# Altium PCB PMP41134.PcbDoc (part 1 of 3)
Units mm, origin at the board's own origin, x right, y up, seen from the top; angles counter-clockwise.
Board outline 252.04 x 132.61 mm, 6 copper layers (Top Layer, Layer 1, Layer 2, Layer 3, Layer 4, Bottom Layer), stack 2.208 mm thick; 221 components, 92 nets, 680 pads, 1197 vias.
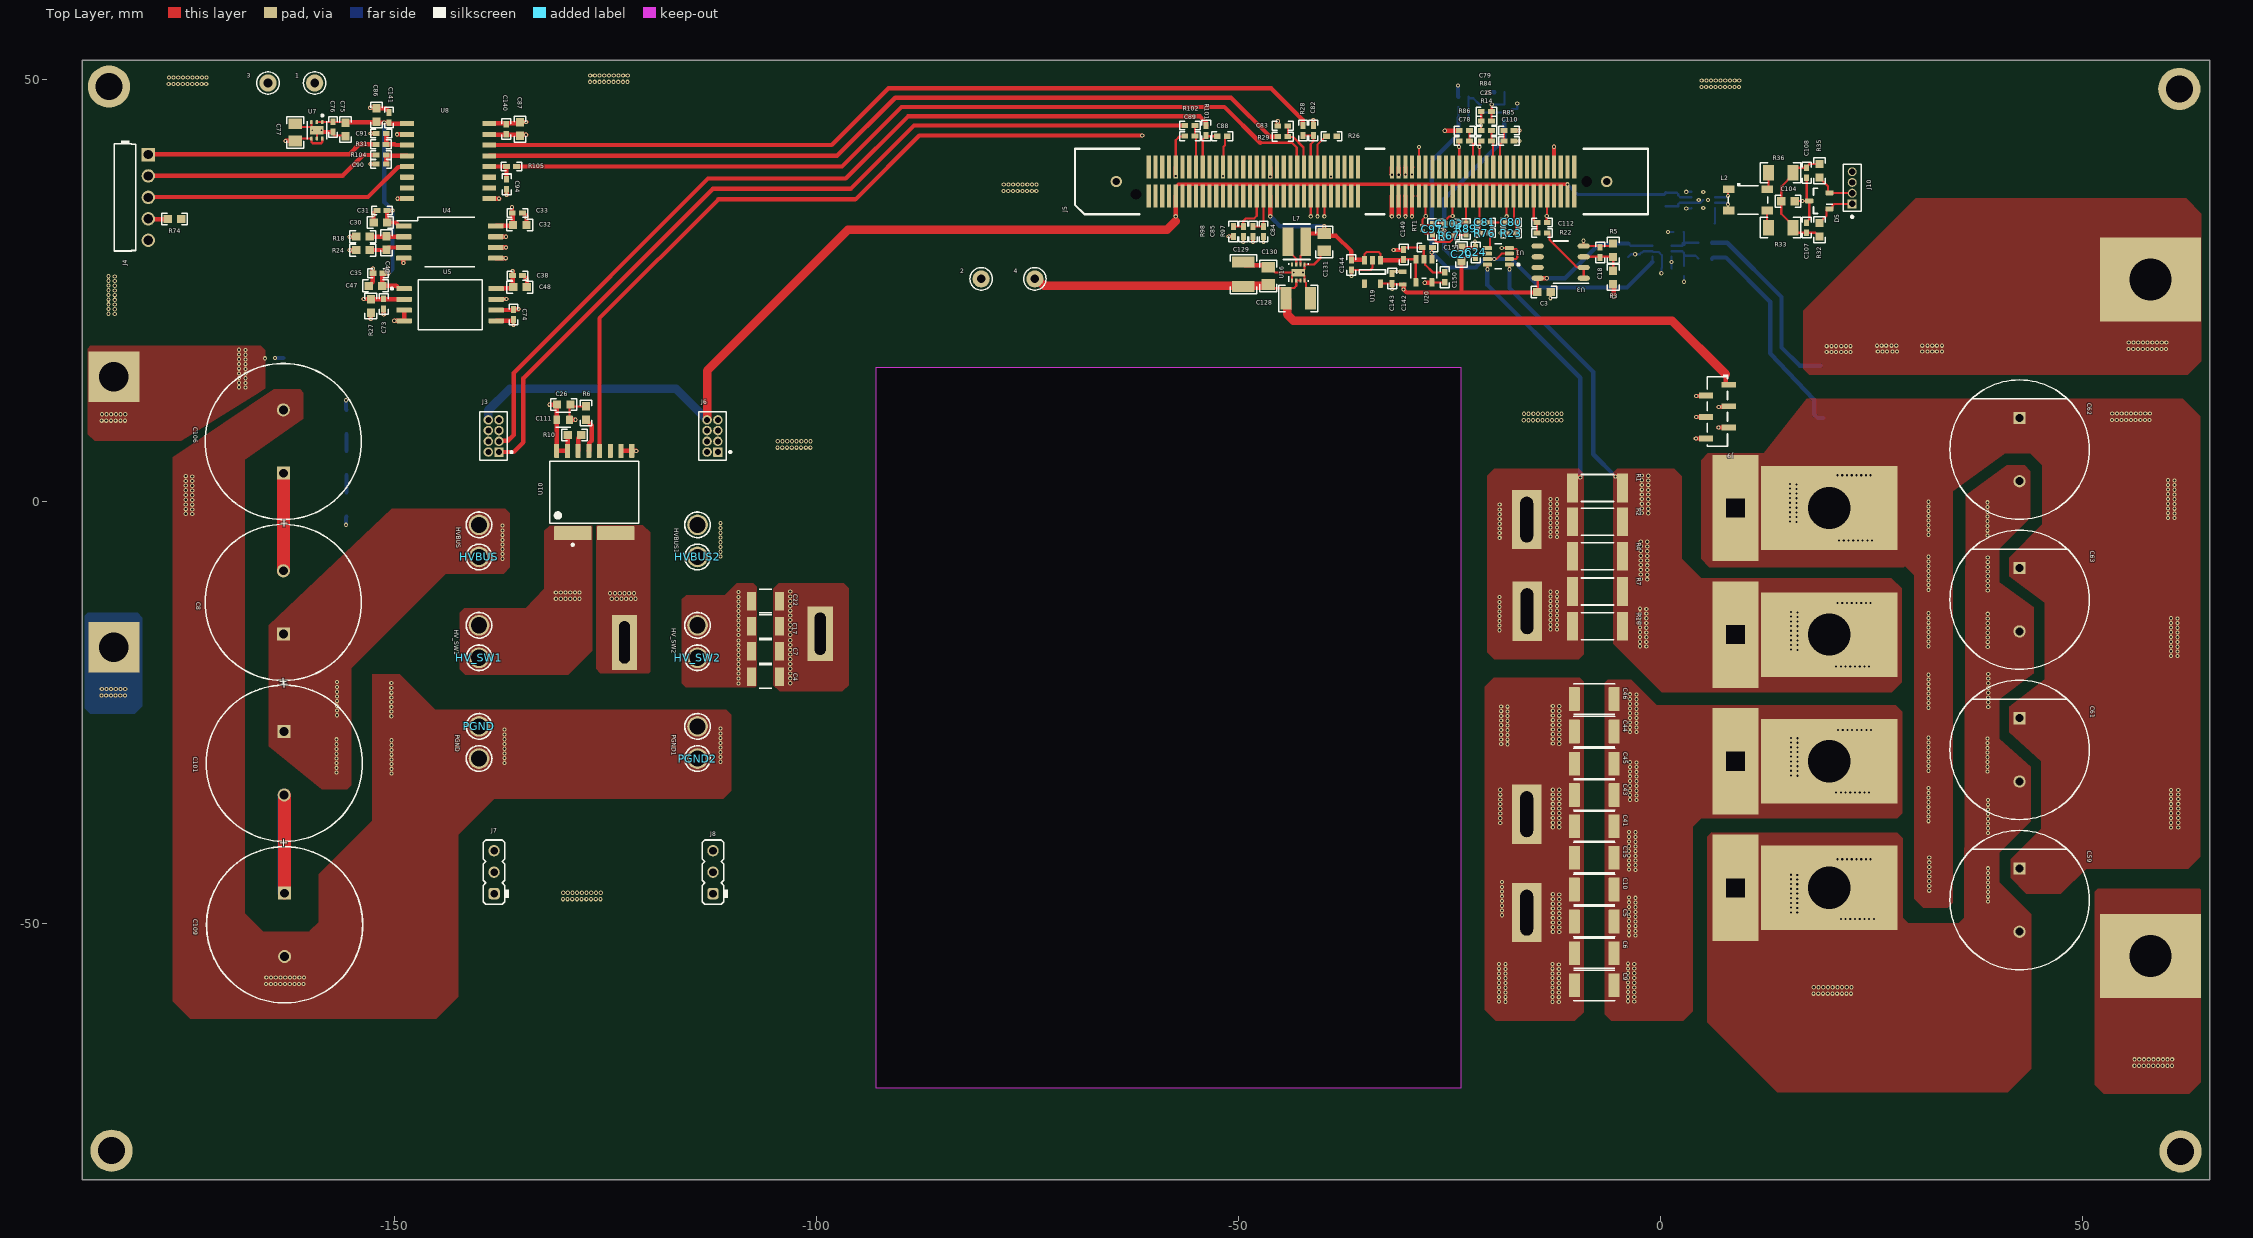
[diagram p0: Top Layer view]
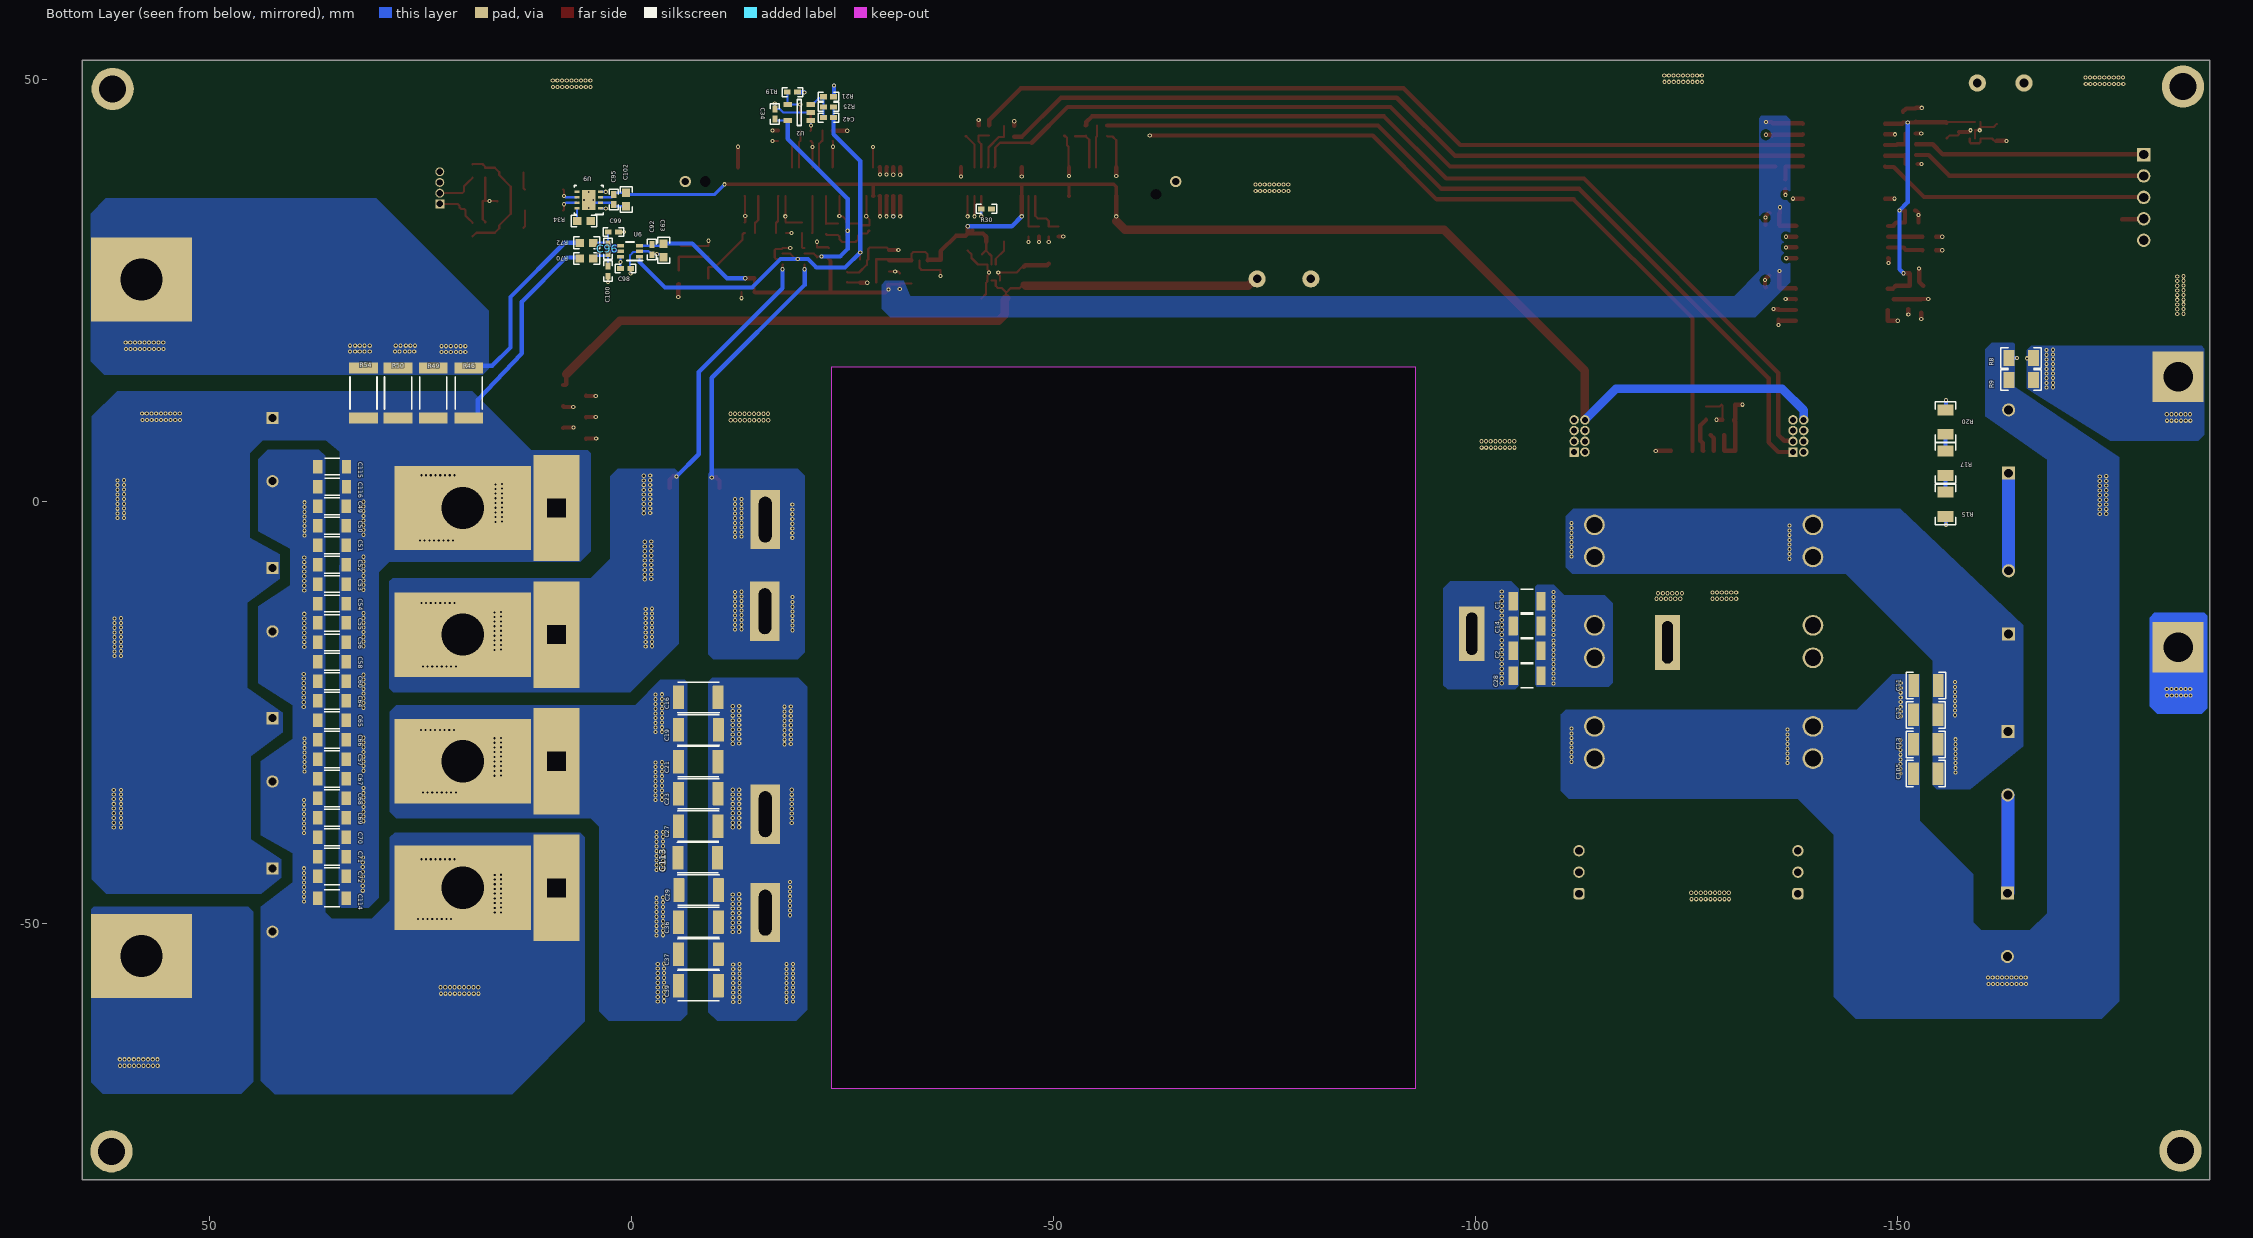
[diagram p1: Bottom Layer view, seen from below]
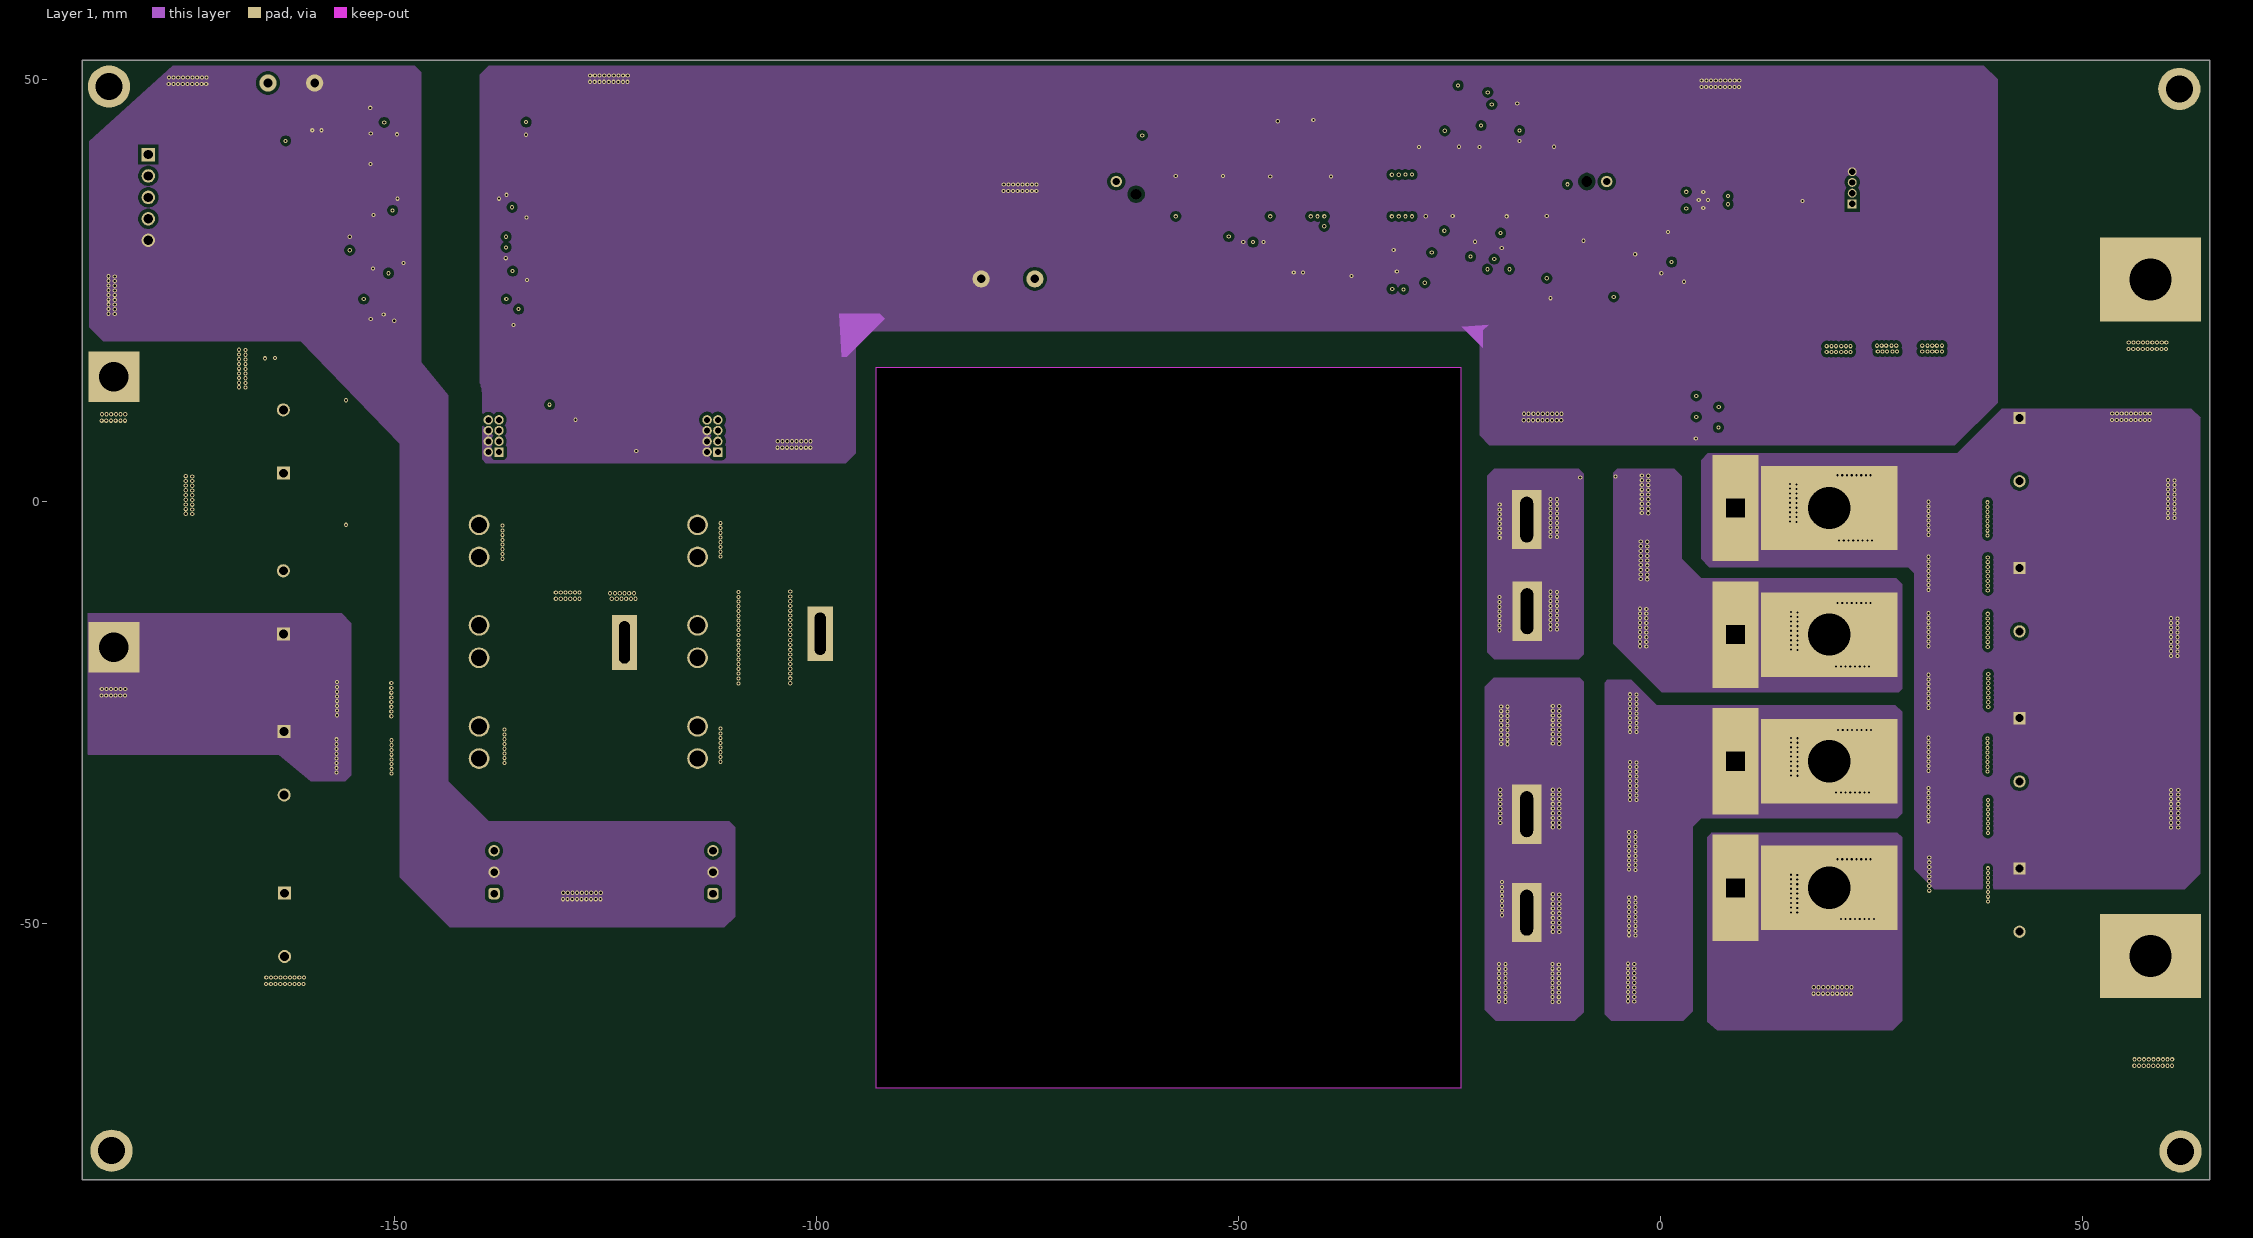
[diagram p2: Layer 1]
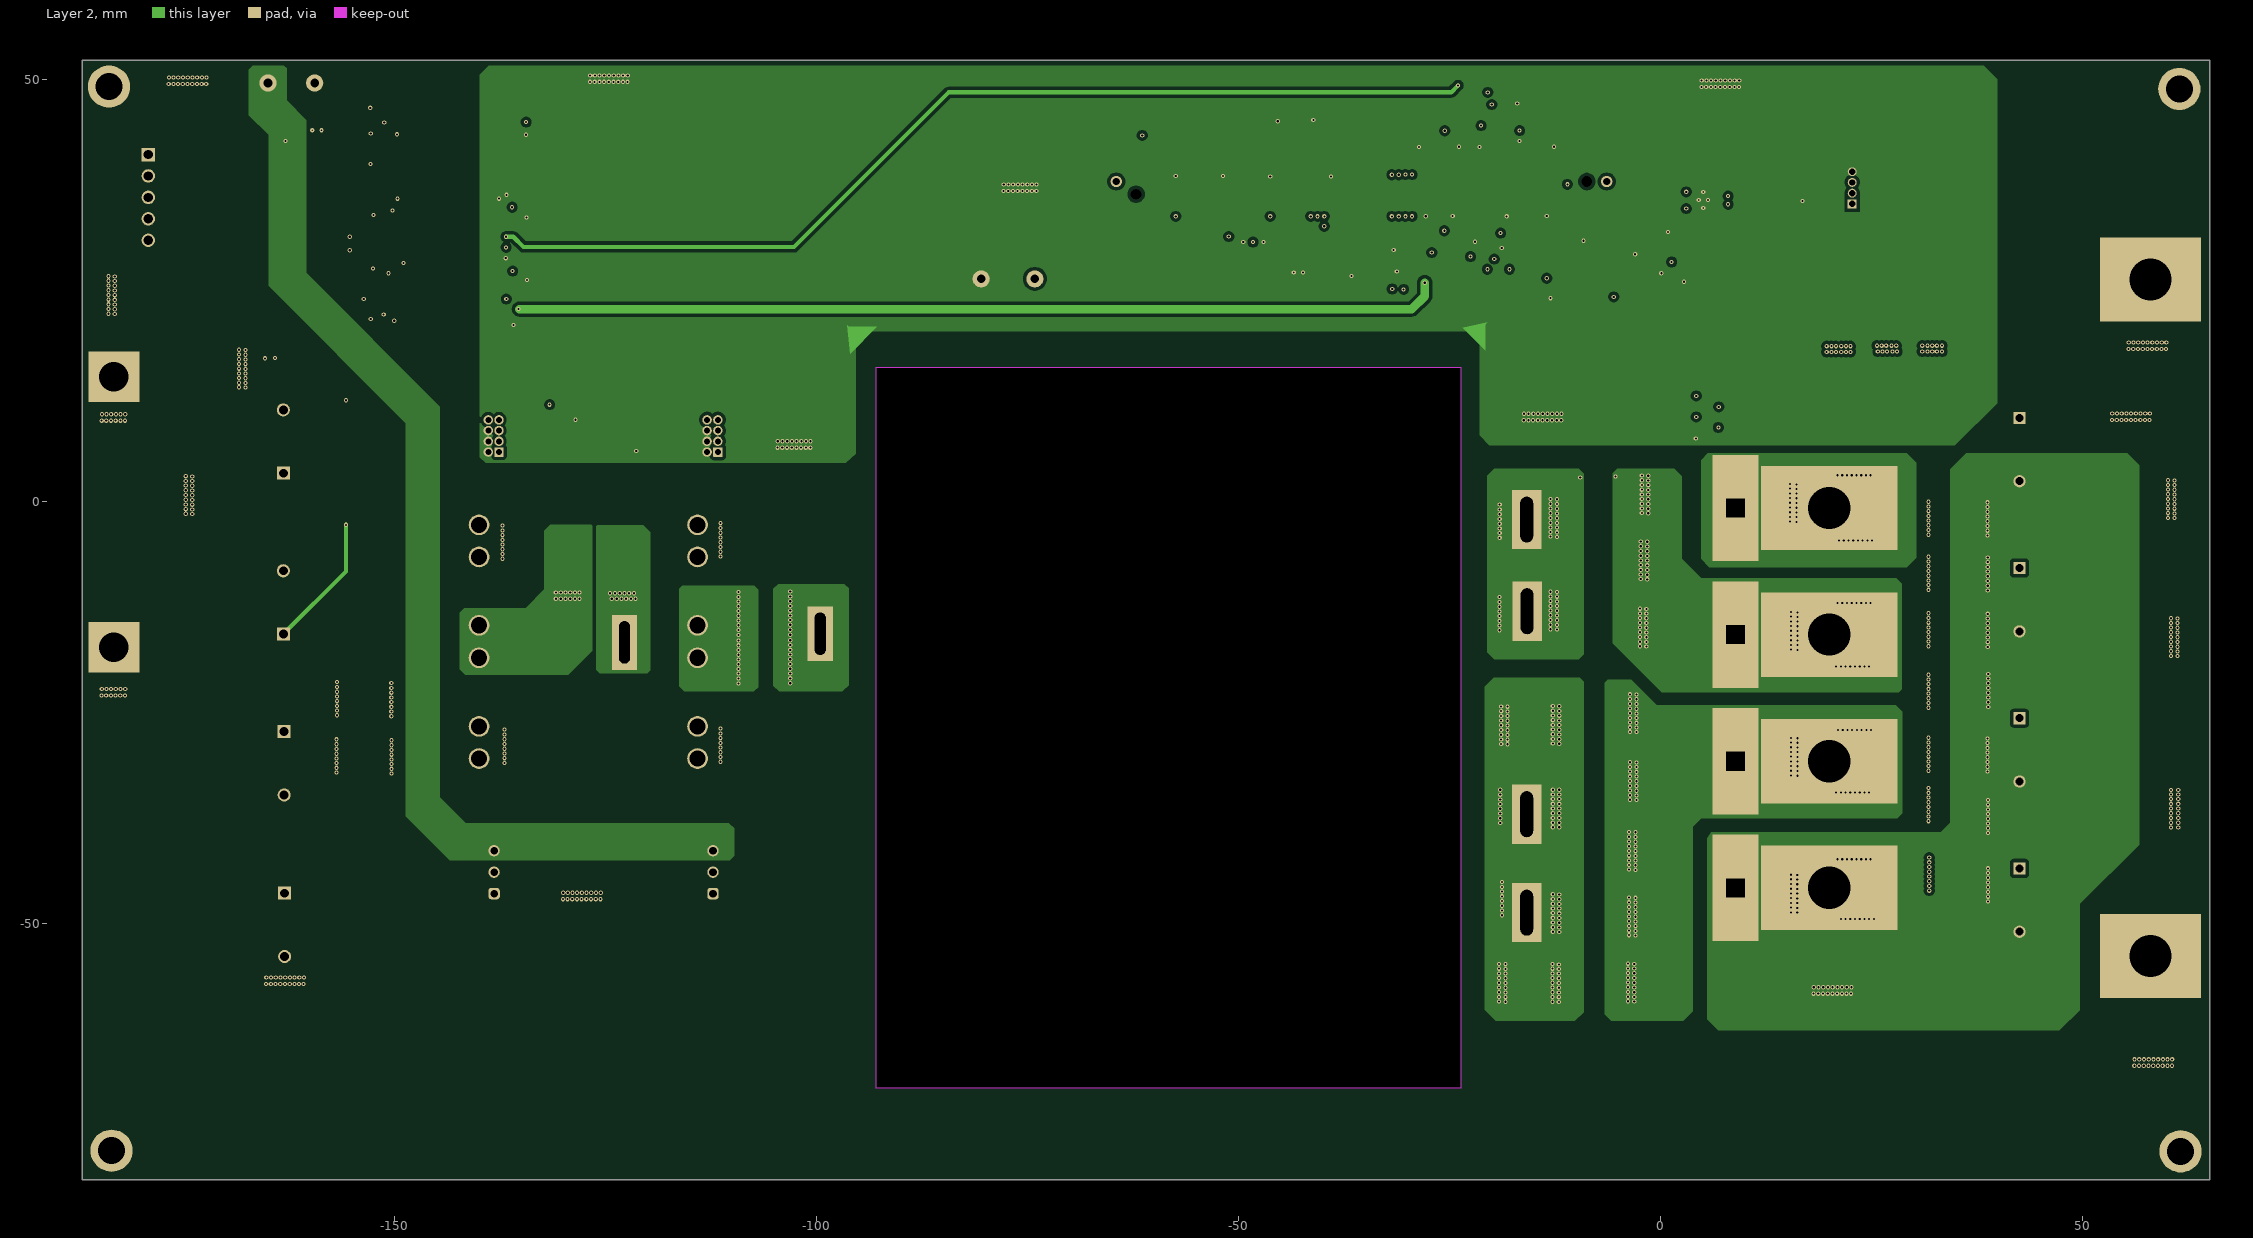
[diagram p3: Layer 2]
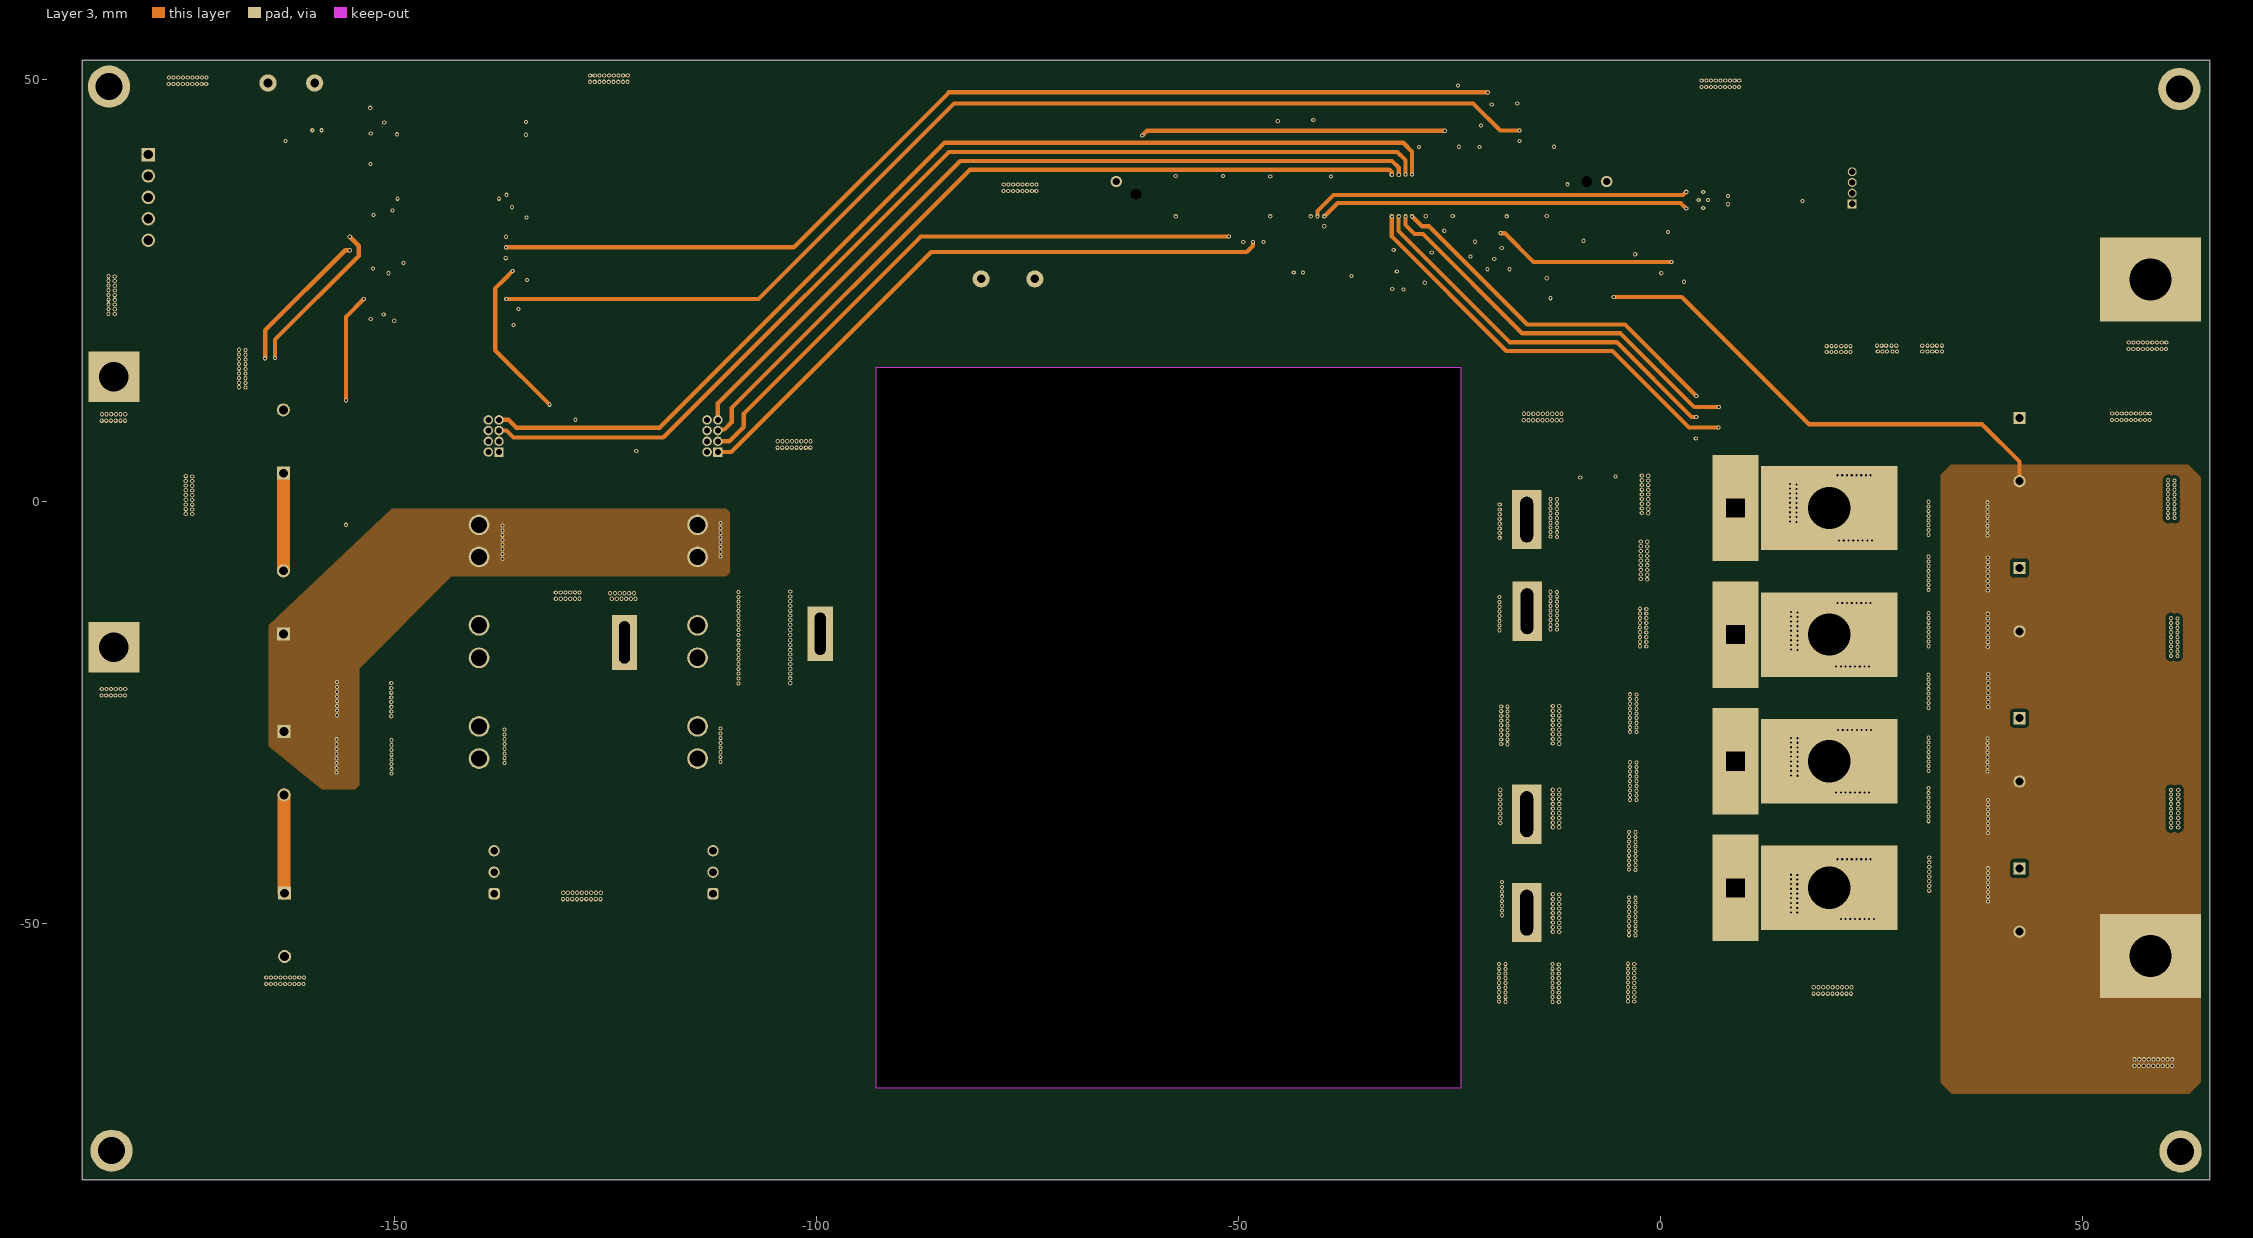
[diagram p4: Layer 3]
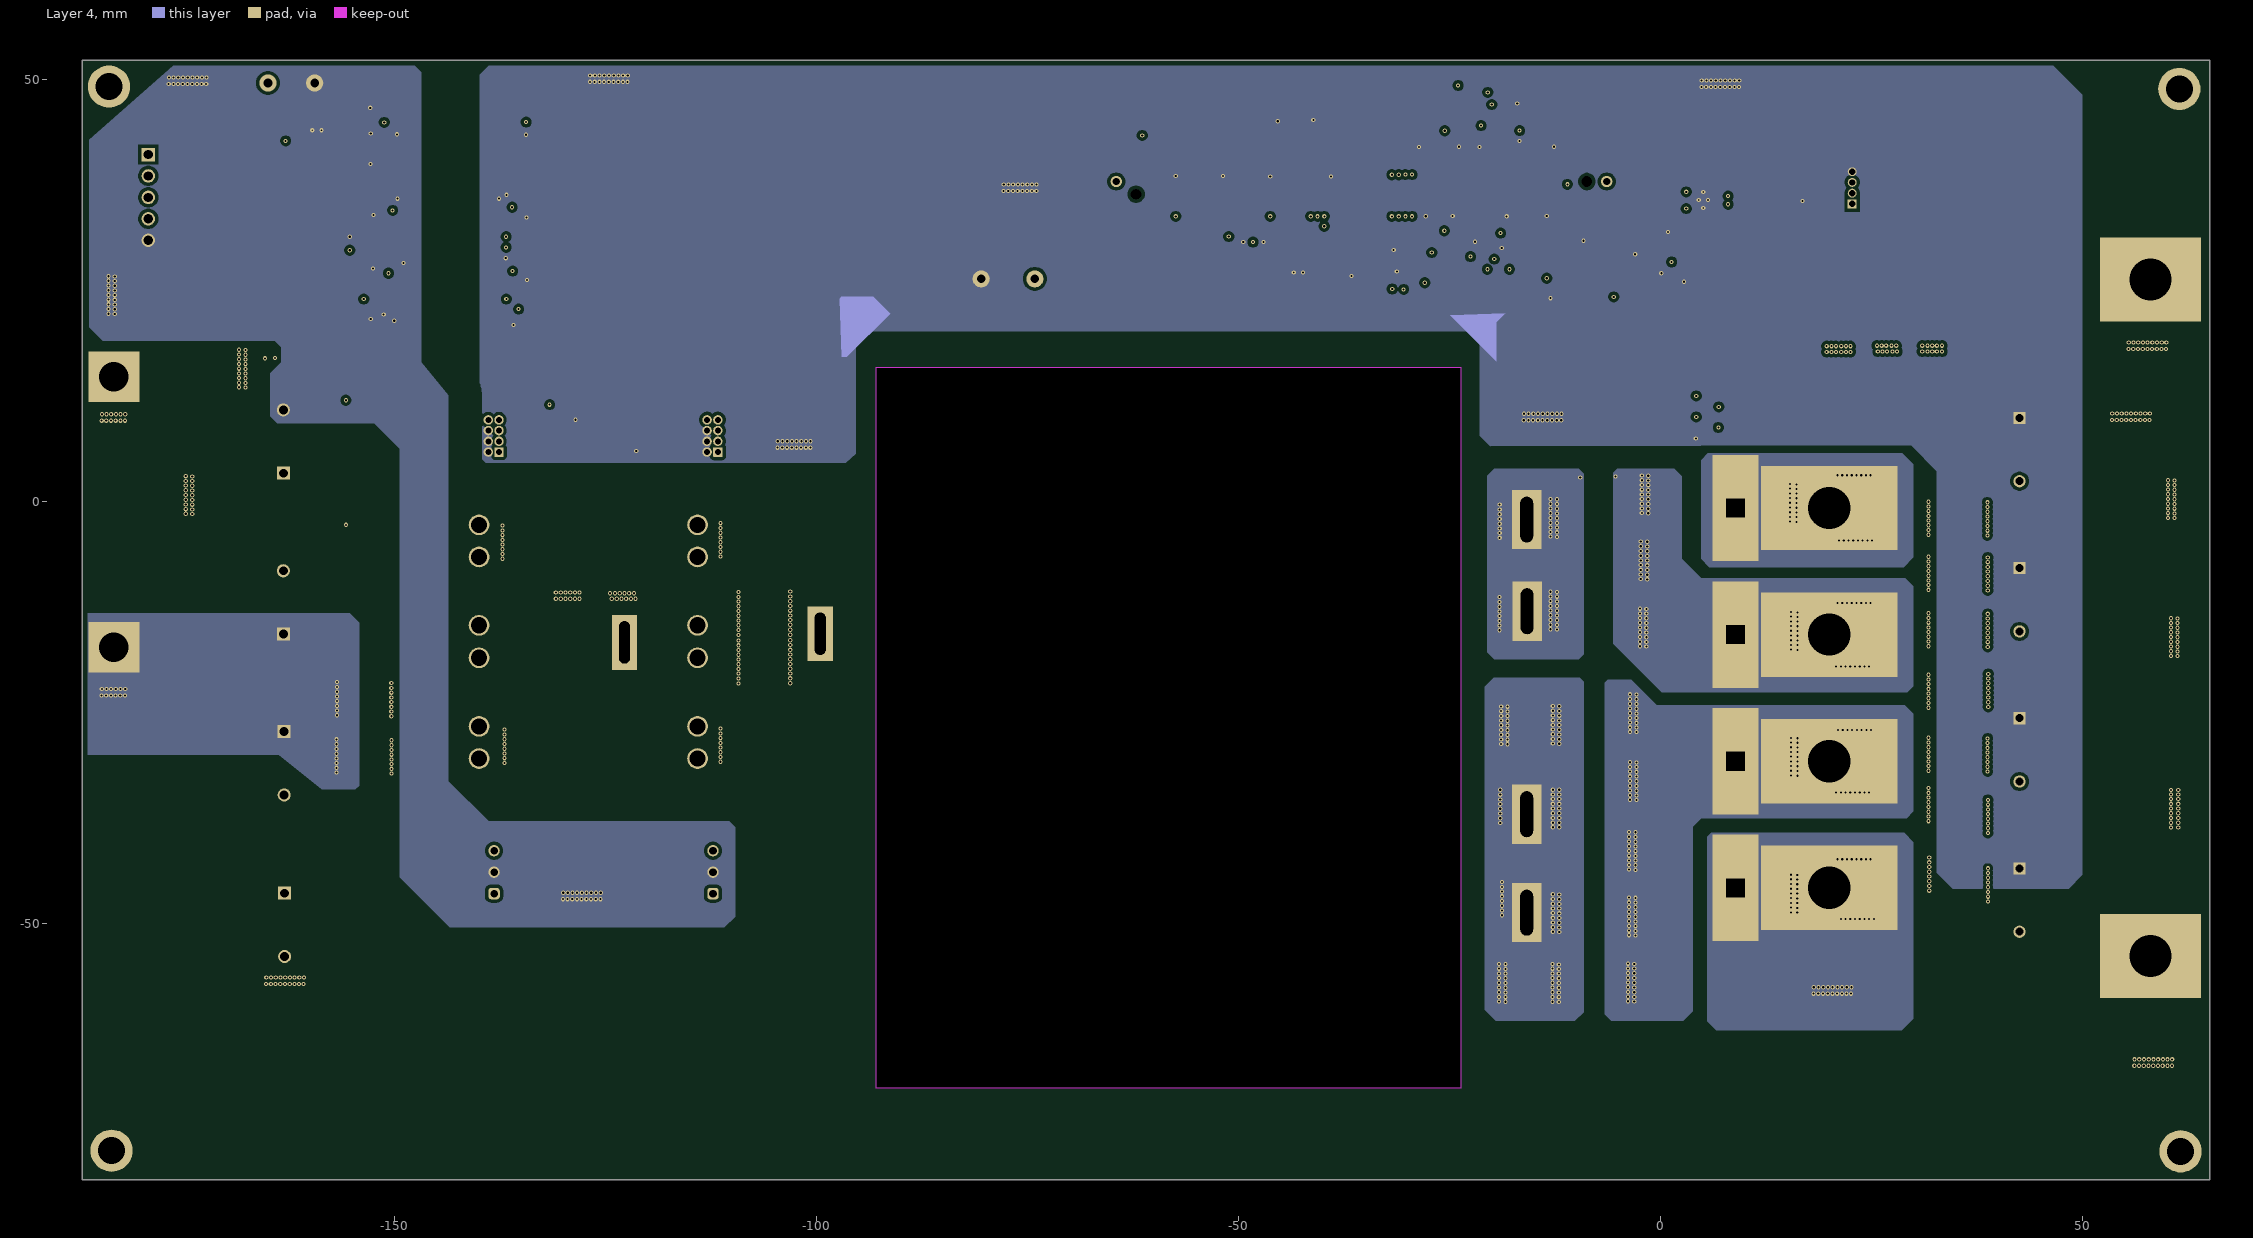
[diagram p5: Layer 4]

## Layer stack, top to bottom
Top Solder: solder mask 0.0102, Solder Resist, Dk 3.5
Top Layer: signal copper 0.07
Dielectric 1: prepreg 0.0711, PP-006, Dk 4.1
Layer 1: signal copper 0.07
Dielectric 3: prepreg 0.0711, PP-006, Dk 4.1
Layer 2: signal copper 0.07
Dielectric1: core 1.5037, FR-4 High Tg, Dk 4.8
Layer 3: signal copper 0.07
Dielectric 4: prepreg 0.0711, PP-006, Dk 4.1
Layer 4: signal copper 0.07
Dielectric 2: prepreg 0.0711, PP-006, Dk 4.1
Bottom Layer: signal copper 0.07
Bottom Solder: solder mask 0.0102, Solder Resist, Dk 3.5

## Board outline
-187.02,-80.289 65.024,-80.289 65.024,52.324 -187.02,52.324
cut-out: -92.964,-69.444 -92.964,15.926 -23.724,15.926 -23.724,-69.444

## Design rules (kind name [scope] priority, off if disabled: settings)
AcuteAngle [All] p1: minimum=4.50000000000000E+0001 checktracksonly=FALSE
AssemblyTestPointUsage [All] p1: valid=2
BoardOutlineClearance BoardOutlineClearance_MountingHoles [OnCopper and InComponentClass('Mounting Holes')] p1: gap=1 ignorepadtopadclearanceinfootprint=FALSE
BoardOutlineClearance BoardOutlineClearance_Poly [OnCopper and IsPoly] p2: gap=0.635 ignorepadtopadclearanceinfootprint=FALSE
BoardOutlineClearance [OnCopper and Not InComponentClass('Logo') and not InComponentClass('FiducialMark') and not InRegion(1000,500,4000,800) and not InPoly] p3: gap=0.254 ignorepadtopadclearanceinfootprint=FALSE
Clearance Clearance_4 [InNet('48Vo+') And OnLayer('Bottom Layer') vs InNet('SGND') And OnLayer('Bottom Layer')] p1: gap=1 ignorepadtopadclearanceinfootprint=TRUE
Clearance Clearance_3 [InNet('48Vo+') And OnLayer('Top Layer') vs InNet('SGND') And OnLayer('Top Layer')] p2: gap=1.016 ignorepadtopadclearanceinfootprint=TRUE
Clearance Clearance_2 [InNet('PGND') vs InNet('SGND')] p3: gap=4 ignorepadtopadclearanceinfootprint=TRUE
Clearance Clearance_1 [InNet('HVBUS') vs InNet('PGND')] p4: gap=1.524 ignorepadtopadclearanceinfootprint=TRUE
Clearance Clearance_Keepouts [((IsTrack Or IsArc) And Not InPoly) And IsFree and IsKeepOut vs ((IsTrack Or IsArc) And Not InPoly) And IsFree and IsKeepOut] p5: gap=0 ignorepadtopadclearanceinfootprint=FALSE
Clearance Clearance_Poly [InPolygon] p6: gap=0.381 ignorepadtopadclearanceinfootprint=TRUE
Clearance Clearance_FiducialMark [IsKeepOut and InComponentClass('FiducialMark') vs IsPad and InComponentClass('FiducialMark')] p7: gap=0 ignorepadtopadclearanceinfootprint=FALSE
Clearance [All] p8: gap=0.2 ignorepadtopadclearanceinfootprint=TRUE
ComponentClearance ComponentClearance_MountingHoles_FiducialMarks [InComponentClass('Mounting Holes') vs InComponentClass('FiducialMark')] p1: gap=1.27 collisioncheckmode=3 verticalgap=0.254 showdistances=FALSE
ComponentClearance ComponentClearance_Shunt [InComponentClass('Header') vs InComponentClass('Shunt')] p2: gap=0 collisioncheckmode=3 verticalgap=0 showdistances=FALSE
ComponentClearance ComponentClearance_Logo [InComponentClass('Logo')] p3: gap=0.762 collisioncheckmode=3 verticalgap=0.254 showdistances=FALSE
ComponentClearance ComponentClearance_ScrewToNut [(HasFootprint('NY PMS 440 0025 PH')) vs (HasFootprint('Keystone_1902C'))] p4: gap=0.127 collisioncheckmode=3 verticalgap=0.254 showdistances=FALSE
ComponentClearance ComponentClearance_MountingHoles [InComponentClass('Mounting Holes')] p5: gap=2.54 collisioncheckmode=3 verticalgap=2540 showdistances=FALSE
ComponentClearance ComponentClearance_SmallPassives [HasFootprint('0201*') or HasFootprint('0402*') or HasFootprint('0508') or HasFootprint('0603*') or HasFootprint('0612') or HasFootprint('0805*') or HasFootprint('0815*') or HasFootprint('0830*') or HasFootprint('1206*') or HasFootprint('1210*') or HasFootprint('1808*') or HasFootprint('1812*') or HasFootprint('1825*') or HasFootprint('2010*') or HasFootprint('2220*') or HasFootprint('2225*') or HasFootprint('2512*') or HasFootprint('2728*') or HasFootprint('3518*') vs HasFootprint('0201*') or HasFootprint('0402*') or HasFootprint('0508') or HasFootprint('0603*') or HasFootprint('0612') or HasFootprint('0805*') or HasFootprint('0815*') or HasFootprint('0830*') or HasFootprint('1206*') or HasFootprint('1210*') or HasFootprint('1808*') or HasFootprint('1812*') or HasFootprint('1825*') or HasFootprint('2010*') or HasFootprint('2220*') or HasFootprint('2225*') or HasFootprint('2512*') or HasFootprint('2728*') or HasFootprint('3518*')] p6: gap=0.38 collisioncheckmode=3 verticalgap=0.254 showdistances=FALSE
ComponentClearance ComponentClearance_THtoSMT [IsThruComponent vs IsSMTComponent] p7: gap=0.762 collisioncheckmode=3 verticalgap=0.762 showdistances=FALSE
ComponentClearance ComponentClearance_THtoTH [IsThruComponent vs IsThruComponent] p8: gap=0.508 collisioncheckmode=3 verticalgap=0.762 showdistances=FALSE
ComponentClearance [All] p9: gap=0.203 collisioncheckmode=3 verticalgap=0.203 showdistances=FALSE
DiffPairsRouting [All] p1: maxlimit=2.54 minlimit=0.254 mostfreqgap=0.254 toplayer_minwidth=0.381 toplayer_maxwidth=0.381 toplayer_prefwidth=0.381 midlayer1_minwidth=0.381 midlayer1_maxwidth=0.381 midlayer1_prefwidth=0.381 midlayer2_minwidth=0.381 midlayer2_maxwidth=0.381 midlayer2_prefwidth=0.381 midlayer3_minwidth=0.381 midlayer3_maxwidth=0.381 midlayer3_prefwidth=0.381 midlayer4_minwidth=0.381 midlayer4_maxwidth=0.381 midlayer4_prefwidth=0.381 bottomlayer_minwidth=0.381 bottomlayer_maxwidth=0.381 bottomlayer_prefwidth=0.381 maxuncoupledlength=25.4
FabricationTestPointUsage TestPointUsage [All] p1: valid=2 allowmultiple=FALSE
FabricationTestpoint Testpoint [All] p1: side=3 testpointundercomponent=TRUE minsize=1.016 maxsize=2.54 preferedsize=1.524 minholesize=0 maxholesize=1.016 preferedholesize=0.813 testpointgrid=0.025 allowsidetop=TRUE allowsidebottom=TRUE usegrid=TRUE gridtolerance=0
FanoutControl Fanout_LCC [IsLCC] p1: bgadir=Out bgaviamode=Centered fanoutstyle=Auto fanoutdirection=Alternating viagrid=0.025 // Fanout_LCC (Default Rule)
FanoutControl Fanout_BGA [IsBGA] p2: bgadir=Out bgaviamode=Centered fanoutstyle=Auto fanoutdirection=Alternating viagrid=0.025 // Fanout_BGA (Default Rule)
FanoutControl Fanout_Default [All] p4: bgadir=Out bgaviamode=Centered fanoutstyle=Auto fanoutdirection=Alternating viagrid=0.025 // Fanout_Default (Default Rule)
FanoutControl Fanout_Small [(CompPinCount < 5)] p5: bgadir=Out bgaviamode=Centered fanoutstyle=Auto fanoutdirection=OutThenIn viagrid=0.025 // Fanout_Small (Default Rule)
Height [All] p1: minheight=0 maxheight=254 prefheight=12.7
HoleSize [All] p1: absolutevalues=TRUE maxlimit=12.725 minlimit=0.2 maxpercent=80.000 minpercent=20.000
MinimumAnnularRing MinimumAnnularRing_ThermalPadVias [IsVia and InAnyComponent] p1: minimumring=0.15
MinimumAnnularRing [All] p2: minimumring=0.1
MinimumSolderMaskSliver MinimumSolderMaskSliver_Logo [InComponentClass('Logo') vs InComponentClass('Logo')] p1: minsoldermaskwidth=0.018
MinimumSolderMaskSliver [All] p2: minsoldermaskwidth=0.1
PlaneConnect [All] p1: planeconnectstyle=Direct reliefexpansion=0.254 reliefentries=4 reliefconductorwidth=0.254 reliefairgap=0.254
PolygonConnect [All] p1: connectstyle=Direct reliefconductorwidth=0.254 reliefentries=4 polygonreliefangle="90 Angle" airgapwidth=0.254
RoutingVias ThermalPadVias [IsVia and InAnyComponent] p1: holewidth=0.2 width=0.5 viastyle="Through Hole" minholewidth=0.2 minwidth=0.5 maxholewidth=0.33 maxwidth=0.6
RoutingVias [All] p2: holewidth=0.406 width=0.864 viastyle="Through Hole" minholewidth=0.2 minwidth=0.254 maxholewidth=1.016 maxwidth=1.651
SilkToBoardRegionClearance [Not ((IsComment or IsDesignator) And (Hide <> 'False')) and not InRegion(1000,500,4000,800)] p1:
SilkToSilkClearance SilkToSilkClearance_Pb-FreeLogo [(HasFootprint('Pb-Free_Overlay_Medium') OR HasFootprint('Pb-Free_Overlay_Small')) vs (HasFootprint('Pb-Free_Overlay_Medium') OR HasFootprint('Pb-Free_Overlay_Small'))] p1: silktosilkclearance=0
SilkToSilkClearance [All] p2: silktosilkclearance=0.1
SilkToSolderMaskClearance SilkToComponentPadClearance [(IsPad or IsFill or IsRegion) and InAnycomponent] p1: minsilkscreentomaskgap=0.127 clearancetoexposedcopper=TRUE
SilkToSolderMaskClearance "Silk to Solder Mask Opening" [All] p2: minsilkscreentomaskgap=0.1 clearancetoexposedcopper=FALSE
SolderMaskExpansion [All] p1: expansion=0.05 istentingtop=FALSE
UnRoutedNet [All] p1: checkbadconnections=TRUE
Width [All] p1: maxlimit=2.54 minlimit=0.152 preferedwidth=0.254 checkconnectedcopper=TRUE
13 further rules are at their usual default settings.

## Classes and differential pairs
net class MV: NetR15_1
component class PMP41134_sheet2: 1 2 3 4 C75 C76 C77 C78 C79 C80 C81 C82 C83 C84 C85 C86 C87 C88 C89 C90 C91 C92 C93 C94 C95 C96 C97 C98 C99 C100 C102 C103 C104 C107 C108 C110 C112 C128 C129 C130 C131 C140 C141 C142 C143 C144 C149 C150 C151 D5 HV_SW1 HV_SW2 HVBUS HVBUS1 HVBUS2 J3 J4 J5 J6 J7 J8 J9 J10 L2 L7 PGND PGND1 PGND2 R22 R23 R26 R28 R29 R30 R31 R32 R33 R34 R35 R36 R67 R70 R72 R74 R76 R84 R85 R86 R89 R97 R98 R101 R102 R104 R105 RT1 U6 U7 U8 U9 U16 U19 U20
component class Header: J4 J10

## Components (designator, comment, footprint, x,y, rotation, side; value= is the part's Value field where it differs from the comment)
1 "5001" Keystone5001 -159.48,49.624 r90 top
2 "5001" Keystone5001 -80.523,26.416 r90 top
3 "5000" Keystone5000 -165.013,49.624 r90 top
4 "5000" Keystone5000 -74.168,26.416 r90 top
C1 "C3225C0G3A103J250AC" FP-C3225C0G3A472J200AC_1210-MFG -106.146,-11.76 r0 bottom value=10nF
C2 "C3225C0G3A103J250AC" FP-C3225C0G3A472J200AC_1210-MFG -106.146,-17.628 r0 bottom value=10nF
C3 "CL10B104KO8NNNC" 0603 -13.862,24.858 r0 top value=0.1uF
C4 "C3225C0G3A103J250AC" FP-C3225C0G3A472J200AC_1210-MFG -106.07,-20.701 r0 top value=10nF
C5 "C4532C0G2E104J320KN" FP-C4532C0G2E104J320KN_1812-MFG -7.895,-49.707 r0 top value=100nF
C6 "C4532C0G2E104J320KN" FP-C4532C0G2E104J320KN_1812-MFG -7.895,-53.466 r0 top value=100nF
C7 "C3225C0G3A103J250AC" FP-C3225C0G3A472J200AC_1210-MFG -106.07,-17.704 r0 top value=10nF
C8 "450QXW220MEFC18X50" QXW_1800x5000 -163.195,-11.913 r90 top value=220uF
C9 "C4532C0G2E104J320KN" FP-C4532C0G2E104J320KN_1812-MFG -7.895,-57.276 r0 top value=100nF
C10 "C4532C0G2E104J320KN" FP-C4532C0G2E104J320KN_1812-MFG -7.895,-45.922 r0 top value=100nF
C11 "CGA6L1X7T2J104K160AC" 1210_200 -153.4,-21.763 r0 bottom value=0.1uF
C12 "CGA6L1X7T2J104K160AC" 1210_200 -153.392,-25.222 r0 bottom value=0.1uF
C13 "CGA6L1X7T2J104K160AC" 1210_200 -153.392,-28.723 r0 bottom value=0.1uF
C14 "C3225C0G3A103J250AC" FP-C3225C0G3A472J200AC_1210-MFG -106.146,-14.707 r0 bottom value=10nF
C15 "C4532C0G2E104J320KN" FP-C4532C0G2E104J320KN_1812-MFG -7.895,-42.138 r0 top value=100nF
C16 "C4532C0G2E104J320KN" FP-C4532C0G2E104J320KN_1812-MFG -7.97,-23.165 r0 bottom value=100nF
C17 "C3225C0G3A103J250AC" FP-C3225C0G3A472J200AC_1210-MFG -106.07,-14.757 r0 top value=10nF
C18 "GRM1555C1H471JA01D" 0402 -7.19,29.56 r90 top value=470pF
C19 "C4532C0G2E104J320KN" FP-C4532C0G2E104J320KN_1812-MFG -7.98,-27.008 r0 bottom value=100nF
C20 "CGA3E1X7R1C105K080AC" 0603 -23.62,29.309 r90 top value=1uF
C21 "C4532C0G2E104J320KN" FP-C4532C0G2E104J320KN_1812-MFG -7.954,-30.767 r0 bottom value=100nF
C22 "C3225C0G3A332J200AE" FP-C3225C0G3A472J200AC_1210-MFG -106.07,-11.76 r0 top value=3.3nF
C23 "C4532C0G2E104J320KN" FP-C4532C0G2E104J320KN_1812-MFG -7.97,-34.569 r0 bottom value=100nF
C24 "GRM155R71E104KE14D" 0402 -21.946,29.556 r90 top value=0.1uF
C25 "GCM155R71E103KA37D" 0402 -20.683,46.228 r0 top value=0.01uF
C26 "06033C104KAT2A" 0603 -129.972,11.518 r0 top value=0.1uF
C27 "C4532C0G2E104J320KN" FP-C4532C0G2E104J320KN_1812-MFG -7.954,-38.412 r0 bottom value=100nF
C28 "C3225C0G3A332J200AE" FP-C3225C0G3A472J200AC_1210-MFG -106.146,-20.599 r0 bottom value=3.3nF
C29 "C4532C0G2E104J320KN" FP-C4532C0G2E104J320KN_1812-MFG -8.005,-45.981 r0 bottom value=100nF
C30 "CGA3E1X7R1C105K080AC" 0603 -151.703,33.109 r180 top value=1uF
C31 "GRM155R71E104KE14D" 0402 -151.503,34.526 r180 top value=0.1uF
C32 "CGA3E1X7R1C105K080AC" 0603 -135.185,32.798 r0 top value=1uF
C33 "GRM155R71E104KE14D" 0402 -135.473,34.226 r0 top value=0.1uF
C34 "GRM155R71E104KE14D" 0402 -17.026,45.95 r90 bottom value=0.1uF
C35 "GRM155R71E104KE14D" 0402 -151.985,27.086 r180 top value=0.1uF
C36 "C4532C0G2E104J320KN" FP-C4532C0G2E104J320KN_1812-MFG -7.98,-49.791 r0 bottom value=100nF
C37 "C4532C0G2E104J320KN" FP-C4532C0G2E104J320KN_1812-MFG -7.98,-53.576 r0 bottom value=100nF
C38 "GRM155R71E104KE14D" 0402 -135.459,26.796 r0 top value=0.1uF
C39 "C4532C0G2E104J320KN" FP-C4532C0G2E104J320KN_1812-MFG -7.98,-57.31 r0 bottom value=100nF
C40 "GRM188R71E103KA01D" 0603 -150.978,30.686 r270 top value=0.01uF
C41 "C4532C0G2E104J320KN" FP-C4532C0G2E104J320KN_1812-MFG -7.895,-38.429 r0 top value=100nF
C42 "GCM155R71E103KA37D" 0402 -23.386,45.517 r180 bottom value=0.01uF
C43 "C4532C0G2E104J320KN" FP-C4532C0G2E104J320KN_1812-MFG -7.895,-34.721 r0 top value=100nF
C44 "C4532C0G2E104J320KN" FP-C4532C0G2E104J320KN_1812-MFG -7.895,-27.204 r0 top value=100nF
C45 "C4532C0G2E104J320KN" FP-C4532C0G2E104J320KN_1812-MFG -7.895,-31.013 r0 top value=100nF
C46 "C4532C0G2E104J320KN" FP-C4532C0G2E104J320KN_1812-MFG -7.895,-23.356 r0 top value=100nF
C47 "CGA3E1X7R1C105K080AC" 0603 -152.285,25.601 r180 top value=1uF
C48 "CGA3E1X7R1C105K080AC" 0603 -135.179,25.432 r0 top value=1uF
C49 "GRM31CZ72A475KE11L" 1206_180 35.436,-0.503 r180 bottom value=4.7uF
C50 "GRM31CZ72A475KE11L" 1206_180 35.436,-2.81 r180 bottom value=4.7uF
C51 "GRM31CZ72A475KE11L" 1206_180 35.436,-5.118 r180 bottom value=4.7uF
C52 "GRM31CZ72A475KE11L" 1206_180 35.436,-7.425 r180 bottom value=4.7uF
C53 "GRM31CZ72A475KE11L" 1206_180 35.436,-9.732 r180 bottom value=4.7uF
C54 "GRM31CZ72A475KE11L" 1206_180 35.436,-12.039 r180 bottom value=4.7uF
C55 "GRM31CZ72A475KE11L" 1206_180 35.436,-14.346 r180 bottom value=4.7uF
C56 "GRM31CZ72A475KE11L" 1206_180 35.436,-16.653 r180 bottom value=4.7uF
C57 "GRM31CR72A225KA73L" 1206_190 35.436,-30.495 r180 bottom value=2.2uF
C58 "GRM31CZ72A475KE11L" 1206_180 35.436,-18.96 r180 bottom value=4.7uF
C59 "EGPD800ELL102ML35H" FP-EGPD800ELL102ML35H_RADIAL-MFG 42.485,-47.168 r270 top value=1mF
C60 "GRM31CZ72A475KE11L" 1206_180 35.436,-21.267 r180 bottom value=4.7uF
C61 "EGPD800ELL102ML35H" FP-EGPD800ELL102ML35H_RADIAL-MFG 42.485,-29.379 r270 top value=1mF
C62 "EGPD800ELL102ML35H" FP-EGPD800ELL102ML35H_RADIAL-MFG 42.485,6.198 r270 top value=1mF
C63 "EGPD800ELL102ML35H" FP-EGPD800ELL102ML35H_RADIAL-MFG 42.485,-11.591 r270 top value=1mF
C64 "GRM31CZ72A475KE11L" 1206_180 35.436,-23.574 r180 bottom value=4.7uF
C65 "GRM31CZ72A475KE11L" 1206_180 35.436,-25.881 r180 bottom value=4.7uF
C66 "GRM31CZ72A475KE11L" 1206_180 35.436,-28.188 r180 bottom value=4.7uF
C67 "GRM31CZ72A475KE11L" 1206_180 35.436,-32.803 r180 bottom value=4.7uF
C68 "GRM31CZ72A475KE11L" 1206_180 35.436,-35.11 r180 bottom value=4.7uF
C69 "GRM31CZ72A475KE11L" 1206_180 35.436,-37.417 r180 bottom value=4.7uF
C70 "GRM31CZ72A475KE11L" 1206_180 35.436,-39.724 r180 bottom value=4.7uF
C71 "GRM31CZ72A475KE11L" 1206_180 35.436,-42.031 r180 bottom value=4.7uF
C72 "GRM31CZ72A475KE11L" 1206_180 35.436,-44.338 r180 bottom value=4.7uF
C73 "C0402C101J3GACTU" 0402 -151.31,23.455 r270 top value=100pF
C74 "GRM155R71E104KE14D" 0402 -135.936,22.205 r90 top value=0.1uF
C75 "GRM188Z71C475KE21D" 0603 -155.822,44.118 r90 top value=4.7uF
C76 "GRM155R71E104KE14D" 0402 -157.306,44.426 r270 top value=0.1uF
C77 "GRM219R71E105KA88D" 0805_HV -161.786,43.768 r90 top value=1uF
C78 "CL05B102KB5NNNC" 0402 -23.283,42.754 r0 top value=1000pF
C79 "GRM155R71E104KE14D" 0402 -20.683,42.754 r180 top value=0.1uF
C80 "GRM155R71E104KE14D" 0402 -17.746,33.098 r180 top value=0.1uF
C81 "CL05B102KB5NNNC" 0402 -20.845,33.098 r0 top value=1000pF
C82 "CL05B102KB5NNNC" 0402 -41.175,43.993 r90 top value=1000pF
C83 "CL05B102KB5NNNC" 0402 -44.795,44.543 r180 top value=1000pF
C84 "CL05B102KB5NNNC" 0402 -47.071,32.034 r270 top value=1000pF
C85 "CL05B102KB5NNNC" 0402 -49.471,32.034 r270 top value=1000pF
C86 "885012206052" 0603 -152.171,45.822 r90 top value=1uF
C87 "885012206052" 0603 -135.157,44.151 r90 top value=1uF
C88 "CL05B102KB5NNNC" 0402 -51.969,43.318 r0 top value=1000pF
C89 "CL05B102KB5NNNC" 0402 -55.799,43.33 r180 top value=1000pF
C90 "CL05B102KB5NNNC" 0402 -151.603,40.035 r180 top value=1000pF
C91 "CL05B102KB5NNNC" 0402 -151.595,43.63 r180 top value=1000pF
C92 "GRM155R71E104KE14D" 0402 -2.464,29.887 r90 bottom value=0.1uF
C93 "CGA3E1X7R1C105K080AC" 0603 -3.866,29.805 r90 bottom value=1uF
C94 "CL05B102KB5NNNC" 0402 -136.742,37.624 r270 top value=1000pF
C95 "GRM155R71E104KE14D" 0402 2.053,35.815 r270 bottom value=0.1uF
C96 "GRM155R71E333KA88D" 0402 2.738,29.99 r90 bottom value=0.033uF
C97 "CGA2B2X7R1H471K050BA" 0402 -27.071,32.302 r90 top value=470pF
C98 "CC0402JRNPO9BN101" 0402 0.653,27.639 r180 bottom value=100pF
C99 "CL05B102KB5NNNC" 0402 2.103,31.962 r180 bottom value=1000pF
C100 "CL05B102KB5NNNC" 0402 2.738,27.33 r270 bottom value=1000pF
C101 "450QXW220MEFC18X50" QXW_1800x5000 -163.093,-30.972 r270 top value=220uF
C102 "GRM188Z71C475KE21D" 0603 0.58,35.815 r270 bottom value=4.7uF
C103 "GRM155R71E104KE14D" 0402 -25.092,32.966 r0 top value=0.1uF
C104 "GCM188R72A472KA37D" 0603 15.06,35.615 r180 top value=4700pF
C105 "CGA6L1X7T2J104K160AC" 1210_200 -153.392,-32.203 r0 bottom value=0.1uF
C106 "450QXW220MEFC18X50" QXW_1800x5000 -163.195,7.15 r90 top value=220uF
C107 "CC0402JRNPO9BN101" 0402 17.271,32.481 r90 top value=100pF
C108 "CC0402JRNPO9BN101" 0402 17.271,38.991 r90 top value=100pF
C109 "450QXW220MEFC18X50" QXW_1800x5000 -163.043,-50.105 r270 top value=220uF
C110 "GRM155R71E104KE14D" 0402 -17.997,42.754 r0 top value=0.1uF
C111 "CL10B105KA8VPJC" FP-CL10B105KA8VPJC_0603-MFG -130.048,9.718 r0 top value=1µF
C112 "GRM155R71E104KE14D" 0402 -14.069,33.098 r0 top value=0.1uF
C113 "C4532C0G2E104J320KN" FP-C4532C0G2E104J320KN_1812-MFG -7.895,-42.138 r0 bottom value=100nF
C114 "GRM31CZ72A475KE11L" 1206_180 35.436,-46.971 r180 bottom value=4.7uF
C115 "GRM31CZ72A475KE11L" 1206_180 35.408,4.191 r180 bottom value=4.7uF
C116 "GRM31CZ72A475KE11L" 1206_180 35.408,1.803 r180 bottom value=4.7uF
C128 "GRM32ER61C476KE15L" 1210_270 -42.975,24.113 r180 top value=47uF
C129 "GRM32ER61C476KE15L" 1210_270 -49.471,26.969 r270 top value=47uF
C130 "GRM219R71E105KA88D" 0805_HV -46.522,26.771 r90 top value=1uF
C131 "CL21A226KOQNNNE" 0805_HV -39.885,30.779 r270 top value=22uF
C140 "C1005X7R1H104K050BB" 0402 -136.789,44.151 r90 top value=0.1uF
C141 "C1005X7R1H104K050BB" 0402 -150.687,45.515 r90 top value=0.1uF
C142 "CGA3E1X7R1E105K080AC" 0603S -30.569,26.516 r90 top value=1uF
C143 "GRM155R71E104KE14D" 0402 -31.834,26.469 r90 top value=0.1uF
C144 "GRM155R71E104KE14D" 0402 -36.671,28.069 r270 top value=0.1uF
C149 "GRM155R71E104KE14D" 0402 -30.473,29.31 r90 top value=0.1uF
C150 "GRM155R71E104KE14D" 0402 -25.61,26.613 r90 top value=0.1uF
C151 "GRM155R71E104KE14D" 0402 -27.671,30.138 r180 top value=0.1uF
D5 "NUP2105LT1G" SOT-23 18.771,35.662 r180 top value=24V
HV_SW1 "0312-0-15-15-34-27-10-0" Mill-Max_0312-0-15-15-34-27-10-0 -140.005,-14.619 r270 top
HV_SW1 "0312-0-15-15-34-27-10-0" Mill-Max_0312-0-15-15-34-27-10-0 -140.005,-18.466 r270 top
HV_SW2 "0312-0-15-15-34-27-10-0" Mill-Max_0312-0-15-15-34-27-10-0 -114.122,-14.619 r270 top
HV_SW2 "0312-0-15-15-34-27-10-0" Mill-Max_0312-0-15-15-34-27-10-0 -114.122,-18.466 r270 top
HVBUS "0312-0-15-15-34-27-10-0" Mill-Max_0312-0-15-15-34-27-10-0 -140.005,-2.718 r270 top
HVBUS "0312-0-15-15-34-27-10-0" Mill-Max_0312-0-15-15-34-27-10-0 -140.005,-6.528 r270 top
HVBUS1 "0312-0-15-15-34-27-10-0" Mill-Max_0312-0-15-15-34-27-10-0 -114.122,-2.718 r270 top
HVBUS2 "0312-0-15-15-34-27-10-0" Mill-Max_0312-0-15-15-34-27-10-0 -114.122,-6.528 r270 top
J3 "M50-3000445" FP-M50-3000445_CONN_SCKT_STRP8-MFG -138.278,7.81 r90 top
J4 "61300511021" Wurth_61300511021 -179.191,36.07 r270 top
J5 "HSEC8-160-01-L-DV-A-BL" controlCARD-120HSEC -33.628,37.97 r180 top
J6 "M50-3000445" FP-M50-3000445_CONN_SCKT_STRP8-MFG -112.356,7.81 r90 top
J7 "801-41-003-10-001000" Mill-Max_801-41-003-10-001000 -138.227,-43.866 r90 top
J8 "801-41-003-10-001000" Mill-Max_801-41-003-10-001000 -112.293,-43.866 r90 top
J9 "LPPB061NFSC-RC" Sullins_LPPB061NFSC-RC 6.7,10.7 r270 top
J10 "GRPB041VWVN-RC" Sullins_GRPB041VWVN-RC 22.657,37.211 r90 top
L2 "ACT45B-101-2P-TL003" ACT45B 10.312,35.764 r0 top value=100uH
L7 "74438336022" FP-74438336010_SMD2-MFG -43.125,30.81 r0 top
PGND "0312-0-15-15-34-27-10-0" Mill-Max_0312-0-15-15-34-27-10-0 -140.005,-26.594 r270 top
PGND "0312-0-15-15-34-27-10-0" Mill-Max_0312-0-15-15-34-27-10-0 -140.005,-30.404 r270 top
PGND1 "0312-0-15-15-34-27-10-0" Mill-Max_0312-0-15-15-34-27-10-0 -114.122,-26.594 r270 top
PGND2 "0312-0-15-15-34-27-10-0" Mill-Max_0312-0-15-15-34-27-10-0 -114.122,-30.404 r270 top
R1 "CSNL2512FTL500" 2512 -7.518,1.65 r0 top value=0.0005
R2 "CSNL2512FTL500" 2512 -7.518,-2.364 r0 top value=0.0005
R3 "CRCW060347K0FKEA" 0603 -5.649,26.604 r270 top value=47.0k
R4 "CSNL2512FTL500" 2512 -7.518,-6.453 r0 top value=0.0005
R5 "RT0603BRD072K1L" 0603 -5.649,29.808 r270 top value=2.10k
R6 "MCT06030Z0000ZP500" 0603 -127.33,10.516 r270 top value=0
R7 "CSNL2512FTL500" 2512 -7.518,-10.619 r0 top value=0.0005
R8 "CRF1206-FZ-R004ELF" 1206 -164.668,17.052 r0 bottom value=0.004
R9 "CRF1206-FZ-R004ELF" 1206 -164.668,14.435 r0 bottom value=0.004
R10 "MCT06030Z0000ZP500" 0603 -128.715,7.925 r180 top value=0
R14 "RC0402FR-074K7L" 0402 -20.671,45.145 r180 top value=4.70k
R15 "ERJ-8ENF2003V" 1206 -155.716,-0.307 r270 bottom value=200k
R16 "CSNL2512FTL500" 2512 -7.518,-14.733 r0 top value=0.0005
R17 "ERJ-8ENF2003V" 1206 -155.716,4.596 r270 bottom value=200k
R18 "CRCW060310R0FKEA" 0603 -153.778,31.411 r0 top value=10.0
R19 "RC0402FR-074K7L" 0402 -19.108,48.541 r0 bottom value=4.70k
R20 "ERJ-8ENF2003V" 1206 -155.716,9.461 r270 bottom value=200k
R21 "RC0402FR-074K7L" 0402 -23.386,47.991 r0 bottom value=4.70k
R22 "CRCW0402100RFKED" 0402 -14.069,31.851 r0 top value=100
R23 "CRCW0402100RFKED" 0402 -17.746,31.839 r180 top value=100
R24 "CRCW060310R0FKEA" 0603 -153.778,29.811 r0 top value=10.0
R25 "RC0402FR-074K7L" 0402 -23.386,46.8 r0 bottom value=4.70k
R26 "RC0402JR-070RL" 0402 -39.006,43.318 r180 top value=0
R27 "RT0603BRD072K1L" 0603 -152.835,23.205 r90 top value=2.10k
R28 "CRCW0402100RFKED" 0402 -42.399,43.993 r90 top value=100
R29 "CRCW0402100RFKED" 0402 -44.795,43.273 r180 top value=100
R30 "RC0402JR-070RL" 0402 -42.088,34.722 r180 bottom value=0
R31 "CRCW0402100RFKED" 0402 -151.626,42.36 r180 top value=100
R32 "RC0603JR-070RL" 0603 18.771,32.241 r90 top value=0
R33 "CRCW120660R0KNEAIF" 1206 14.175,32.481 r180 top value=60
R34 "MCT06030Z0000ZP500" 0603 5.577,33.271 r0 bottom value=0
R35 "RC0603JR-070RL" 0603 18.771,39.229 r270 top value=0
R36 "CRCW120660R0KNEAIF" 1206 14.175,38.991 r180 top value=60
R46 "CSNL2512FTL500" 2512 19.218,12.886 r90 bottom value=0.0005
R49 "CSNL2512FTL500" 2512 23.428,12.886 r90 bottom value=0.0005
R50 "CSNL2512FTL500" 2512 27.602,12.903 r90 bottom value=0.0005
R54 "CSNL2512FTL500" 2512 31.691,12.903 r90 bottom value=0.0005
R67 "Resistor" 0402 -25.054,31.547 r0 top value=10.0k
R70 "CRCW060310R0FKEA" 0603 5.262,28.817 r180 bottom value=10.0
R72 "CRCW060310R0FKEA" 0603 5.262,30.693 r180 bottom value=10.0
R74 "MCT06030Z0000ZP500" 0603 -176.098,33.53 r180 top value=0
R76 "CRCW0402100RFKED" 0402 -20.845,31.851 r0 top value=100
R84 "CRCW0402100RFKED" 0402 -20.671,43.974 r0 top value=100
R85 "CRCW0402100RFKED" 0402 -17.997,43.989 r0 top value=100
R86 "CRCW0402100RFKED" 0402 -23.283,43.974 r0 top value=100
R89 "CRCW0402100RFKED" 0402 -23.086,32.331 r90 top value=100
R97 "CRCW0402100RFKED" 0402 -48.321,32.034 r90 top value=100
R98 "CRCW0402100RFKED" 0402 -50.648,32.034 r90 top value=100
R101 "CRCW0402100RFKED" 0402 -53.873,43.993 r270 top value=100
R102 "CRCW0402100RFKED" 0402 -55.799,44.58 r0 top value=100
R104 "CRCW0402100RFKED" 0402 -151.61,41.082 r180 top value=100
R105 "CRCW0402100RFKED" 0402 -136.168,39.731 r180 top value=100
RT1 "TMP6131DECR" DEC0002A -28.255,32.446 r270 top
U1 "INA241A4IDDF" DDF0008A-MFG -19.257,29.088 r180 top
U2 "OPA320AIDBVR" DBV0005A_N -19.921,46.128 r0 bottom
U3 "TLV9062IDR" D0008A_N -11.871,28.401 r180 top
U4 "AMC1302QDWVRQ1" DWV0008A -143.478,30.776 r0 top
U5 "AMC0311RDWVR" DWV0008A-MFG -143.429,23.359 r0 top
U6 "INA199A2DCKT" DCK0006A_N 0.116,29.692 r0 bottom
U7 "TLV76733DRVT" DRV0006A-MFG -159.211,44.023 r270 top
U8 "ISO7742DWR" DW0016B_HV -143.677,40.366 r0 top
U9 "TCAN1042HDRBRQ1" DRB0008F 5.027,35.764 r0 bottom
U10 "TMCS1133B2QDVGR" DVG0010A-MFG -126.365,1.168 r90 top
U16 "TPS62163DSGR" DSG0008A -42.949,27.169 r90 top
U19 "TLV71333PQDBVRQ1" DBV0005A_N -34.178,27.239 r270 top
U20 "REF2033AIDDCR" DDC0005A_N -28.086,27.373 r270 top

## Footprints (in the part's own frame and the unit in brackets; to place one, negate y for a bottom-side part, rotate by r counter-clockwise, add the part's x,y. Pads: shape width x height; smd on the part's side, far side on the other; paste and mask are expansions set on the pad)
0402 [mm] "0402 from SM-752 data"
  rect 0.8x0.6 smd: 1(-0.6,0) 2(0.6,0)
  silkscreen extent -1.22,-0.52 1.22,0.52, body extent -0.55,-0.3 0.55,0.3, height 0.6
0603 [mm] "0603 from SM-752 data"
  rect 1x0.95 smd: 1(-0.8,0) 2(0.8,0)
  silkscreen extent -1.52,-0.69 1.52,0.69, body extent -0.87,-0.47 0.87,0.47, height 1
0603S [mil]
  rect 20x35 smd: 1(-30,0) 2(30,0)
  body extent -34,-19 34,19, height 39
0805_HV [mil] "0805 with 30mil clearance between pads"
  rect 50x63 smd: 1(-40,0) 2(40,0)
  silkscreen extent -74,-40 74,40, body extent -43,-29 43,29, height 57
1206 [mm] "1206 from SM-752 data"
  rect 1.3x1.85 smd: 1(-1.45,0) 2(1.45,0)
  silkscreen extent -2.4,-1.21 2.4,1.21, body extent -1.7,-0.9 1.7,0.9, height 1.35
1206_180 [mm] "1206_180"
  rect 1.1x1.6 smd: 1(-1.7,0) 2(1.7,0)
  silkscreen extent -0.9,-1 0.9,1, body extent -1.75,-0.95 1.75,0.95, height 1.8
1206_190 [mm] "1206_190"
  rect 1.1x1.6 smd: 1(-1.7,0) 2(1.7,0)
  silkscreen extent -0.9,-1 0.9,1, body extent -1.75,-0.95 1.75,0.95, height 1.9
1210_200 [mm] "1210"
  rect 1.3x2.7 smd: 1(-1.45,0) 2(1.45,0)
  silkscreen extent -2.32,-1.57 2.32,1.57, body extent -1.7,-1.35 1.7,1.35, height 2
1210_270 [mm] "1210"
  rect 1.3x2.7 smd: 1(-1.45,0) 2(1.45,0)
  silkscreen extent -2.32,-1.57 2.32,1.57, body extent -1.7,-1.35 1.7,1.35, height 2.7
2512 [mm] "Chip Resistor, Body 6.3x3.2mm, IPC Medium Density"
  rect 1.3x3.4 smd: 1(-2.95,0) 2(2.95,0)
  silkscreen extent -1.9,-1.6 1.9,1.6, body extent -3.22,-1.67 3.22,1.67, height 0.71
ACT45B [mm] "SMD, 4-Leads, Body 4.7 x 3.7 mm"
  rect 1.35x0.9 smd: 1(-2.275,1.25) 2(-2.275,-1.25) 3(2.275,-1.25) 4(2.275,1.25)
  silkscreen extent -2.35,-1.7 2.35,2, body extent -2.35,-1.7 2.35,1.7, height 3
controlCARD-120HSEC [mm] "Pads are not numbered according to Samtec datasheet."
  rect 0.5x2.724 smd: 1(-23.357,-1.678) 2(-23.357,1.722) 3(-22.557,-1.678) 4(-22.557,1.722) 5(-21.757,-1.678) 6(-21.757,1.722) 7(-20.957,-1.678) 8(-20.957,1.722) 9(-20.157,-1.678) 10(-20.157,1.722) 11(-19.357,-1.678) 12(-19.357,1.722) 13(-18.557,-1.678) 14(-18.557,1.722) 15(-17.757,-1.678) 16(-17.757,1.722) 17(-16.957,-1.678) 18(-16.957,1.722) 19(-16.157,-1.678) 20(-16.157,1.722) 21(-15.357,-1.678) 22(-15.357,1.722) 23(-14.557,-1.678) 24(-14.557,1.722) 25(-13.757,-1.678) 26(-13.757,1.722) 27(-12.957,-1.678) 28(-12.957,1.722) 29(-12.157,-1.678) 30(-12.157,1.722) 31(-11.357,-1.678) 32(-11.357,1.722) 33(-10.557,-1.678) 34(-10.557,1.722) 35(-9.757,-1.678) 36(-9.757,1.722) 37(-8.957,-1.678) 38(-8.957,1.722) 39(-8.157,-1.678) 40(-8.157,1.722) 41(-7.357,-1.678) 42(-7.357,1.722) 43(-6.557,-1.678) 44(-6.557,1.722) 45(-5.757,-1.678) 46(-5.757,1.722) 47(-4.957,-1.678) 48(-4.957,1.722) 49(-4.157,-1.678) 50(-4.157,1.722) 51(-3.357,-1.678) 52(-3.357,1.722) 53(-2.557,-1.678) 54(-2.557,1.722) 55(-1.757,-1.678) 56(-1.757,1.722) 57(2.243,-1.678) 58(2.243,1.722) 59(3.043,-1.678) 60(3.043,1.722) 61(3.843,-1.678) 62(3.843,1.722) 63(4.643,-1.678) 64(4.643,1.722) 65(5.443,-1.678) 66(5.443,1.722) 67(6.243,-1.678) 68(6.243,1.722) 69(7.043,-1.678) 70(7.043,1.722) 71(7.843,-1.678) 72(7.843,1.722) 73(8.643,-1.678) 74(8.643,1.722) 75(9.443,-1.678) 76(9.443,1.722) 77(10.243,-1.678) 78(10.243,1.722) 79(11.043,-1.678) 80(11.043,1.722) 81(11.843,-1.678) 82(11.843,1.722) 83(12.643,-1.678) 84(12.643,1.722) 85(13.443,-1.678) 86(13.443,1.722) 87(14.243,-1.678) 88(14.243,1.722) 89(15.043,-1.678) 90(15.043,1.722) 91(15.843,-1.678) 92(15.843,1.722) 93(16.643,-1.678) 94(16.643,1.722) 95(17.443,-1.678) 96(17.443,1.722) 97(18.243,-1.678) 98(18.243,1.722) 99(19.043,-1.678) 100(19.043,1.722) 101(19.843,-1.678) 102(19.843,1.722) 103(20.643,-1.678) 104(20.643,1.722) 105(21.443,-1.678) 106(21.443,1.722) 107(22.243,-1.678) 108(22.243,1.722) 109(23.043,-1.678) 110(23.043,1.722) 111(23.843,-1.678) 112(23.843,1.722) 113(24.643,-1.678) 114(24.643,1.722) 115(25.443,-1.678) 116(25.443,1.722) 117(26.243,-1.678) 118(26.243,1.722) 119(27.043,-1.678) 120(27.043,1.722)
  round 0.025 hole 1.27 unplated mask+0.876: 181(-24.857,0.022) 182(28.543,1.522)
  round 1.348 hole 0.84: 185(-27.207,0.022) 186(30.893,0.022)
  silkscreen extent -32.11,-3.86 35.8,3.9, body extent -31.75,-3.48 35.3,3.52, height 12.35
D0008A_N [mm] "SOIC, 8-Leads, Body 4.9x3.9mm, Pitch 1.27mm, IPC Medium Density"
  oval 1.45x0.6 smd: 1(-2.725,1.905) 2(-2.725,0.635) 3(-2.725,-0.635) 4(-2.725,-1.905) 5(2.725,-1.905) 6(2.725,-0.635) 7(2.725,0.635) 8(2.725,1.905)
  silkscreen extent -3.3,-2.5 0.9,2.5, body extent -3,-2.45 3,2.45, height 1.63
DBV0005A_N [mm] "SOT23, 5-Leads, Body 2.9x1.6mm, Pitch 0.95mm, Lead Span 2.8mm, IPC Medium Density"
  rrect17% 1x0.6 smd: 1(-1.375,0.95) 2(-1.375,0) 3(-1.375,-0.95) 4(1.375,-0.95) 5(1.375,0.95)
  silkscreen extent -0.25,-1.55 0.25,1.55, body extent -1.42,-1.46 1.42,1.46, height 1.09
DCK0006A_N [mm] "SOT23, 6-Leads, Body 2x1.3mm, Pitch 0.65mm, Lead Span 2.1mm, IPC Medium Density"
  rrect25% 0.85x0.4 smd: 1(-1.125,0.65) 2(-1.125,0) 3(-1.125,-0.65) 4(1.125,-0.65) 5(1.125,0) 6(1.125,0.65)
  silkscreen extent -1.5,-1.09 0.51,1.09, body extent -1.14,-1 1.14,1, height 0.95
DDC0005A_N [mm]
  rrect17% 1x0.6 smd: 1(-1.375,0.95) 2(-1.375,0) 3(-1.375,-0.95) 4(1.375,-0.95) 5(1.375,0.95)
  silkscreen extent -1.25,-1.52 0.88,1.58, body extent -1.41,-1.45 1.41,1.45, height 1.1
DDF0008A-MFG [mm]
  rrect22% 1.05x0.45 smd paste+0 mask+0: 1(-1.3,0.975) 2(-1.3,0.325) 3(-1.3,-0.325) 4(-1.3,-0.975) 5(1.3,-0.975) 6(1.3,-0.325) 7(1.3,0.325) 8(1.3,0.975)
  silkscreen extent -2.5,-1.48 0.4,1.48, body extent -1.92,-1.73 1.92,1.73, height 0.25
DEC0002A [mm] "X1SON-2"
  rrect57% 0.35x0.6 smd paste-0.5 mask-0.05: 1(-0.325,0) 2(0.325,0)
  rrect33% 0.3x0.5 on Top Paste: 1S(-0.35,0) 2S(0.35,0)
  body extent -0.5,-0.3 0.5,0.3, height 0.5
DRB0008F [mm] "SON, 8-Leads, Body 3x3mm, Pitch 0.65mm, Thermal Pad 2.4x1.6mm, TI Recommended"
  rrect33% 0.6x0.3 smd: 1(-1.4,0.975) 2(-1.4,0.325) 3(-1.4,-0.325) 4(-1.4,-0.975) 5(1.4,-0.975) 6(1.4,-0.325) 7(1.4,0.325) 8(1.4,0.975)
  rrect9% 1.47x1.07 on Bottom Paste: 9(0,-0.635) 9(0,0.635)
  rrect6% 1.6x2.4 smd paste-1.2: 9(0,0)
  silkscreen extent -1.73,-1.73 1.73,1.73, body extent -1.5,-1.5 1.5,1.5, height 0.77
DRV0006A-MFG [mm]
  rrect33% 0.45x0.3 smd paste+0 mask+0: 1(-0.975,0.65) 2(-0.975,0) 3(-0.975,-0.65) 4(0.975,-0.65) 5(0.975,0) 6(0.975,0.65)
  rrect10% 1x1.6 smd paste-1000 mask+0: 7(0,0)
  silkscreen extent -1.87,-1.17 1.05,1.17, body extent -1.3,-1.15 1.3,1.15, height 0.25
DSG0008A [mm] "SON, 8-Leads, Body 2x2mm, Pitch 0.5mm, Thermal Pad 1.6x0.9mm, TI Recommended"
  rrect40% 0.5x0.25 smd: 1(-0.95,0.75) 2(-0.95,0.25) 3(-0.95,-0.25) 4(-0.95,-0.75) 5(0.95,-0.75) 6(0.95,-0.25) 7(0.95,0.25) 8(0.95,0.75)
  rrect14% 0.9x0.7 on Top Paste: 9(0,0.45) 9(0,-0.45)
  rrect11% 0.9x1.6 smd paste-0.45: 9(0,0)
  silkscreen extent -1.07,-1.15 1.07,1.15, body extent -1,-1 1,1, height 0.77
DVG0010A-MFG [mm]
  rrect6% 1.65x4.41 smd paste+0 mask+0: 1(-4.875,2.54) 2(-4.875,-2.54)
  rrect17% 1.65x0.6 smd paste+0 mask+0: 3(4.875,-4.445) 4(4.875,-3.175) 5(4.875,-1.905) 6(4.875,-0.635) 7(4.875,0.635) 8(4.875,1.905) 9(4.875,3.175) 10(4.875,4.445)
  silkscreen extent -6.37,-5.25 3.67,5.25, body extent -5.8,-5.5 5.8,5.5, height 0.25
DW0016B_HV [mm] "SOIC-16, HV/isolation option"
  rrect17% 1.65x0.6 smd: 1(-4.875,4.445) 2(-4.875,3.175) 3(-4.875,1.905) 4(-4.875,0.635) 5(-4.875,-0.635) 6(-4.875,-1.905) 7(-4.875,-3.175) 8(-4.875,-4.445) 9(4.875,-4.445) 10(4.875,-3.175) 11(4.875,-1.905) 12(4.875,-0.635) 13(4.875,0.635) 14(4.875,1.905) 15(4.875,3.175) 16(4.875,4.445)
  body extent -5.17,-5.15 5.17,5.15, height 2.59
DWV0008A [mm] "SOIC, 8-Leads, Body 5.95x7.6mm (max), Pitch 1.27mm"
  rrect17% 1.8x0.6 smd: 1(-5.45,1.905) 2(-5.45,0.635) 3(-5.45,-0.635) 4(-5.45,-1.905) 5(5.45,-1.905) 6(5.45,-0.635) 7(5.45,0.635) 8(5.45,1.905)
  silkscreen extent -6.25,-2.95 2.98,2.95, body extent -5.77,-2.92 5.77,2.93, height 2.67
DWV0008A-MFG [mm]
  rrect17% 1.8x0.6 smd paste+0 mask+0: 1(-5.45,1.905) 2(-5.45,0.635) 3(-5.45,-0.635) 4(-5.45,-1.905) 5(5.45,-1.905) 6(5.45,-0.635) 7(5.45,0.635) 8(5.45,1.905)
  silkscreen extent -7.02,-2.98 3.8,2.98, body extent -5.75,-2.93 5.75,2.93, height 2.8
FP-74438336010_SMD2-MFG [mm]
  rrect8% 1.3x3.4 smd paste+0 mask+0: 1(-1.05,0) 2(1.05,0)
  silkscreen extent -1.6,-2.1 1.6,2.1, body extent -1.8,-1.8 1.8,1.8, height 0.25
FP-C3225C0G3A472J200AC_1210-MFG [mm]
  rrect9% 1.1x2.2 smd paste+0 mask+0: 1(-1.65,0) 2(1.65,0)
  silkscreen extent -0.72,-1.4 0.72,1.4, body extent -1.6,-1.25 1.6,1.25, height 2.2
FP-C4532C0G2E104J320KN_1812-MFG [mm]
  rrect8% 1.3x2.8 smd paste+0 mask+0: 1(-2.35,0) 2(2.35,0)
  silkscreen extent -2.45,-1.8 2.45,1.8, body extent -3.1,-1.9 3.1,1.9, height 0.25
FP-CL10B105KA8VPJC_0603-MFG [mm]
  rrect13% 0.79x1 smd paste+0 mask+0: 1(-0.755,0) 2(0.755,0)
  silkscreen extent -0.9,-0.87 0.9,0.87, body extent -1.25,-0.6 1.25,0.6, height 0.25
FP-EGPD800ELL102ML35H_RADIAL-MFG [mm]
  rrect7% 1.45x1.45 hole 0.95 paste-1000 mask+0: 1(-3.75,0)
  round 1.45 hole 0.95 paste-1000 mask+0: 2(3.75,0)
  silkscreen extent -8.25,-8.25 8.25,8.25, body extent -8.35,-8.35 8.35,8.35, height 0.25
FP-M50-3000445_CONN_SCKT_STRP8-MFG [mm]
  rrect9% 1.12x1.12 hole 0.7 paste-1000 mask+0: 1(-1.905,-0.635)
  round 1.12 hole 0.7 paste-1000 mask+0: 2(-1.905,0.635) 3(-0.635,-0.635) 4(-0.635,0.635) 5(0.635,-0.635) 6(0.635,0.635) 7(1.905,-0.635) 8(1.905,0.635)
  silkscreen extent -2.89,-2.24 2.89,1.63, body extent -2.99,-1.73 2.99,1.73, height 0.25
Keystone5000 [mil] "For Keystone 500x miniature loop terminals"
  round 80 hole 40: 1(0,0)
  silkscreen extent -52,-52 52,52, body extent -49,-49 49,49, height 182
Keystone5001 [mil] "For Keystone 500x miniature loop terminals"
  round 80 hole 40: 1(0,0)
  silkscreen extent -52,-52 52,52, body extent -49,-49 49,49, height 182
Mill-Max_0312-0-15-15-34-27-10-0 [mm] "Pin Receptacle, .032-.046\" .075\" Dia, Gold, TH"
  round 2.45 hole 1.905: 1(0,0)
  silkscreen extent -1.52,-1.52 1.52,1.52, body extent -1.15,-1.15 1.16,1.15, height 0.46
Mill-Max_801-41-003-10-001000 [mm] "Receptacle, 2.54mm, 3x1, TH"
  rrect50% 1.35x1.35 hole 0.9: 1(-2.54,0)
  round 1.35 hole 0.9: 2(0,0) 3(2.54,0)
  silkscreen extent -3.81,-1.75 3.81,1.27, body extent -3.81,-1.27 3.81,1.27, height 7.01
QXW_1800x5000 [mm] "TH, 2-Leads, Dia 18mm, Lead Sapcing 7.5mm"
  rect 1.55x1.55 hole 1.05: 1(-3.75,0)
  round 1.55 hole 1.05: 2(3.75,0)
  silkscreen extent -9.25,-9.25 9.25,9.25, body extent -9.18,-9.24 9.22,9.23, height 52
SOT-23 [mm] "SOT23, 3-Leads, Body 2.9x1.3mm, Pitch 0.95mm, Lead Span 2.5mm, IPC Medium Density"
  rrect50% 1x0.6 smd: 1(-1.2,0.95) 2(-1.2,-0.95) 3(1.2,0)
  silkscreen extent -1.62,-1.5 0.7,1.5, body extent -1.16,-1.45 1.21,1.45, height 1
Sullins_GRPB041VWVN-RC [mm] "TH, Header, 1.27 mm, 4x1, Straight"
  rect 1.05x1.05 hole 0.75: 1(-1.905,0)
  round 1.05 hole 0.75: 2(-0.635,0) 3(0.635,0) 4(1.905,0)
  silkscreen extent -3.54,-1.07 2.79,1.07, body extent -2.79,-1.07 2.79,1.07, height 4.3
Sullins_LPPB061NFSC-RC [mm] "Receptacle, 1.27mm, 6x1, SMT"
  rect 0.7x1.7 smd: 1(-3.175,1.35) 2(-1.905,-1.35) 3(-0.635,1.35) 4(0.635,-1.35) 5(1.905,1.35) 6(3.175,-1.35)
  silkscreen extent -4.38,-1.2 4.11,1.3, body extent -4.11,-1.65 4.11,1.65, height 4.85
Wurth_61300511021 [mm] "Header, 2.54 mm, 5x1, R/A, TH"
  rect 1.6x1.6 hole 1.1: 1(-5.08,0)
  round 1.6 hole 1.1: 2(-2.54,0) 3(0,0) 4(2.54,0) 5(5.08,0)
  silkscreen extent -6.75,-4.04 6.35,-1.5, body extent -6.35,-10.04 6.35,0.32, height 2.55

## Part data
1 2: library part CMP-0055138-1, "Test Point, Miniature, Black, TH", Color=Black, Manufacturer=Keystone, Supplier Part Number 1=36-5001-ND
3 4: library part CMP-0055137-1, "Test Point, Miniature, Red, TH", Color=Red, Manufacturer=Keystone, Supplier Part Number 1=36-5000-ND
C1 C2 C4 C7 C14 C17: library part CMP-0121422-1, "Multilayer Ceramic Capacitors 10nF ±5% 1000V C0G SMD 1210", Manufacturer=TDK, Operating Temperature Range="-55°C to +125°C", TempCo=30ppm/°C, Temperature Characteristic=C0G, Tolerance_%=0.05%
C3: library part CMP-0007110-5, "CAP, CERM, 0.1 uF, 16 V, +/- 10%, X7R, 0603", Cap_Case=0603, Manufacturer="Samsung Electro-Mechanics", TempCo=X7R, Tolerance_%=10%, Value1=Unknown, Value2=16V, ValueDisplayed=0.1uF
C5 C6 C9 C10 C15 C16 C19 C21 C23 C27 C29 C36 C37 C39 C41 C43 C44 C45 C46 C113: library part CMP-0097363-1, "Multilayer Ceramic Capacitors 100nF ±5% 250V C0G SMD 1812", Manufacturer=TDK, Operating Temperature Range="-55°C to +125°C", TempCo=30ppm/°C, Temperature Characteristic=C0G, Tolerance_%=0.05%, ValueDisplayed=100nF
C8 C101 C106 C109: library part CMP-0009981-2, "CAP, AL, 220 uF, 450 V, +/- 20%, TH", Cap_Case=18x50mm, Manufacturer=Rubycon, Supplier Part Number 1=1189-1380-ND, Tolerance_%=20%, Value1=Unknown, Value2=450V, ValueDisplayed=220uF
C11 C12 C13 C105: library part CMP-0009140-2, "CAP, CERM, 0.1 uF, 630 V, +/- 10%, X7R, AEC-Q200 Grade 1, 1210", Cap_Case=1210, Manufacturer=TDK, Supplier Part Number 1=445-7116-1-ND, TempCo=X7R, Tolerance_%=10%, Value1=Unknown, Value2=630V, ValueDisplayed=0.1uF
C18: library part CMP-0006470-1, "CAP, CERM, 470 pF, 50 V, +/- 5%, C0G/NP0, 0402", Cap_Case=0402, Manufacturer=MuRata, Supplier Part Number 1=490-1297-1-ND, TempCo=C0G/NP0, Tolerance_%=5%, Value1=Unknown, Value2=50V, ValueDisplayed=470pF
C20 C30 C32 C47 C48 C93: library part CMP-0079607-1, "CAP, CERM, 1 µF, 16 V,+/- 10%, X7R, AEC-Q200 Grade 1, 0603", Cap_Case=0603, Manufacturer=TDK, Supplier Part Number 1=445-12539-1-ND, TempCo=X7R, Tolerance_%=10%, Value2=16V, ValueDisplayed=1µF
C22: library part CMP-0121422-1, "Multilayer Ceramic Capacitors 3.3nF ±5% 1000V C0G SMD 1210", Manufacturer=TDK, Operating Temperature Range="-55°C to +125°C", TempCo=30ppm/°C, Temperature Characteristic=C0G, Tolerance_%=0.05%
C24 C31 C33 C34 C35 C38 C74 C76 C79 C80 C92 C95 C103 C110 C112 C143 C144 C149 C150 C151: library part CMP-0006659-2, "CAP, CERM, 0.1 uF, 25 V, +/- 10%, X7R, 0402", Cap_Case=0402, Manufacturer=MuRata, Supplier Part Number 1=490-10698-1-ND, TempCo=X7R, Tolerance_%=10%, Value1=Unknown, Value2=25V, ValueDisplayed=0.1uF
C25 C42: library part CMP-0006352-2, "CAP, CERM, 0.01 uF, 25 V, +/- 10%, X7R, 0402", Cap_Case=0402, Manufacturer=MuRata, Supplier Part Number 1=490-6043-2-ND, TempCo=X7R, Tolerance_%=10%, Value1=Unknown, Value2=25V, ValueDisplayed=0.01uF
C26: library part CMP-0006753-4, "CAP, CERM, 0.1 uF, 25 V, +/- 10%, X7R, 0603", Cap_Case=0603, Manufacturer=AVX, Supplier Part Number 1=478-3714-1-ND, TempCo=X7R, Tolerance_%=10%, Value1="0.05 ohm", Value2=25V, ValueDisplayed=0.1uF
C28: library part CMP-0121422-1, "Multilayer Ceramic Capacitors 3.3nF ±5% 1000V C0G SMD 1210", Manufacturer=TDK, Operating Temperature Range="-55°C to +125°C", Part Number=C3225C0G3A472J200AC, TempCo=30ppm/°C, Temperature Characteristic=C0G, Tolerance_%=0.05%
C40: library part CMP-0007403-4, "CAP, CERM, 0.01 uF, 25 V, +/- 10%, X7R, 0603", Cap_Case=0603, Manufacturer=MuRata, Supplier Part Number 1=490-1520-1-ND, TempCo=X7R, Tolerance_%=10%, Value1=Unknown, Value2=25V, ValueDisplayed=0.01uF
C49 C50 C51 C52 C53 C54 C55 C56 C58 C60 C64 C65 C66 C67 C68 C69 C70 C71 C72 C114 C115 C116: library part CMP-0008802-2, "CAP, CERM, 4.7 uF, 100 V, +/- 10%, X7R, 1206", Cap_Case=1206, Manufacturer=Samsung, TempCo=X7R, Tolerance_%=10%, Value1=Unknown, Value2=100V, ValueDisplayed=4.7uF
C57: library part CMP-0008971-1, "CAP, CERM, 2.2 uF, 100 V, +/- 10%, X7R, 1206_190", Cap_Case=1206, Manufacturer=MuRata, Supplier Part Number 1=490-7209-1-ND, TempCo=X7R, Tolerance_%=10%, Value1=Unknown, Value2=100V
C59 C61 C62 C63: library part CMP-0097417-1, "1000 µF 80 V Aluminum Electrolytic Capacitors Radial, Can 27mOhm @ 100kHz 2000 Hrs @ 135°C", Digikey Part Number=565-EGPD800ELL102ML35H-ND, Leakage Current=2400uA, Manufacturer="United Chemi-Con", Mouser Part Number=661-EGPD800E102ML35H, Operating Temperature Range="-40°C to +135°C", Tolerance_%=20%, ValueDisplayed=1000uF
C73: library part CMP-0006233-2, "CAP, CERM, 100 pF, 25 V, +/- 5%, C0G/NP0, 0402", Cap_Case=0402, Manufacturer=Kemet, Supplier Part Number 1=399-1022-1-ND, TempCo=C0G/NP0, Tolerance_%=5%, Value1=Unknown, Value2=25V, ValueDisplayed=100pF
C75 C102: library part CMP-0064936-4, "CAP, CERM, 4.7 uF, 16 V,+/- 10%, X7R, 0603", Cap_Case=0603, Manufacturer=MuRata, TempCo=X7R, Tolerance_%=10%, Value1=Unknown, Value2=16V, ValueDisplayed=4.7uF
C77 C130: library part CMP-0008217-2, "CAP, CERM, 1 uF, 25 V, +/- 10%, X7R, 0805", Cap_Case=0805, Manufacturer=MuRata, Supplier Part Number 1=GRM219R71E105KA88D-ND, TempCo=X7R, Tolerance_%=10%, Value1=Unknown, Value2=25V, ValueDisplayed=1uF
C78 C81 C82 C83 C84 C85 C88 C89 C90 C91 C94 C99 C100: library part CMP-0860560-1, "CAP, CERM, 1000 pF, 50 V,+/- 10%, X7R, 0402", Cap_Case=0402, Manufacturer="Samsung Electro-Mechanics", TempCo=X7R, Tolerance_%=10%, Value2=50V, ValueDisplayed=1000pF
C86 C87: library part CMP-0006831-4, "CAP, CERM, 1 uF, 16 V, +/- 10%, X7R, 0603", Cap_Case=0603, Manufacturer="Wurth Elektronik", Supplier Part Number 1=710-885012206052, TempCo=X7R, Tolerance_%=10%, Value1=Unknown, Value2=16V, ValueDisplayed=1uF
C96: library part CMP-0006666-2, "CAP, CERM, 0.033 uF, 25 V, +/- 10%, X7R, 0402", Cap_Case=0402, Manufacturer=MuRata, Supplier Part Number 1=490-3253-1-ND, TempCo=X7R, Tolerance_%=10%, Value1=Unknown, Value2=25V, ValueDisplayed=0.033uF
C97: library part CMP-0006320-2, "CAP, CERM, 470 pF, 50 V, +/- 10%, X7R, AEC-Q200 Grade 1, 0402", Cap_Case=0402, Manufacturer=TDK, Supplier Part Number 1=445-6888-1-ND, TempCo=X7R, Tolerance_%=10%, Value1="4.96489 ohm", Value2=50V, ValueDisplayed=470pF
C98 C107 C108: library part CMP-0006303-2, "CAP, CERM, 100 pF, 50 V, +/- 5%, C0G/NP0, 0402", Cap_Case=0402, Manufacturer="Yageo America", Supplier Part Number 1=311-1024-1-ND, TempCo=C0G/NP0, Tolerance_%=5%, Value1=Unknown, Value2=50V, ValueDisplayed=100pF
C104: library part CMP-0079247-1, "CAP, CERM, 4700 pF, 100 V,+/- 10%, X7R, AEC-Q200 Grade 1, 0603", Cap_Case=0603, Manufacturer=MuRata, Supplier Part Number 1=490-4930-1-ND, TempCo=X7R, Tolerance_%=10%, Value2=100V, ValueDisplayed=4700pF
C111: library part CMP-0121052-1, "Cap Ceramic 1uF 25V X7R ±10% Pad SMD 0603 +125°C T/R", Digikey Part Number=1276-CL10B105KA8VPJCCT-ND, Manufacturer=Samsung, Mouser Part Number=187-CL10B105KA8VPJC, Operating Temperature Range="-55°C to +125°C", TempCo=15%, Temperature Characteristic=X7R, Tolerance_%=10%, ValueDisplayed=1uF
